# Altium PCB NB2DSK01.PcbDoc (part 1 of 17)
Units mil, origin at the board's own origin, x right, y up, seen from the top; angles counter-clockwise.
Board outline 11815 x 6500.03 mil, 8 copper layers (Top Layer, MidLayer1, MidLayer2, GND, PWR, MidLayer3, MidLayer4, Bottom Layer), stack 74.62 mil thick; 798 components, 1002 nets, 3927 pads, 3182 vias.
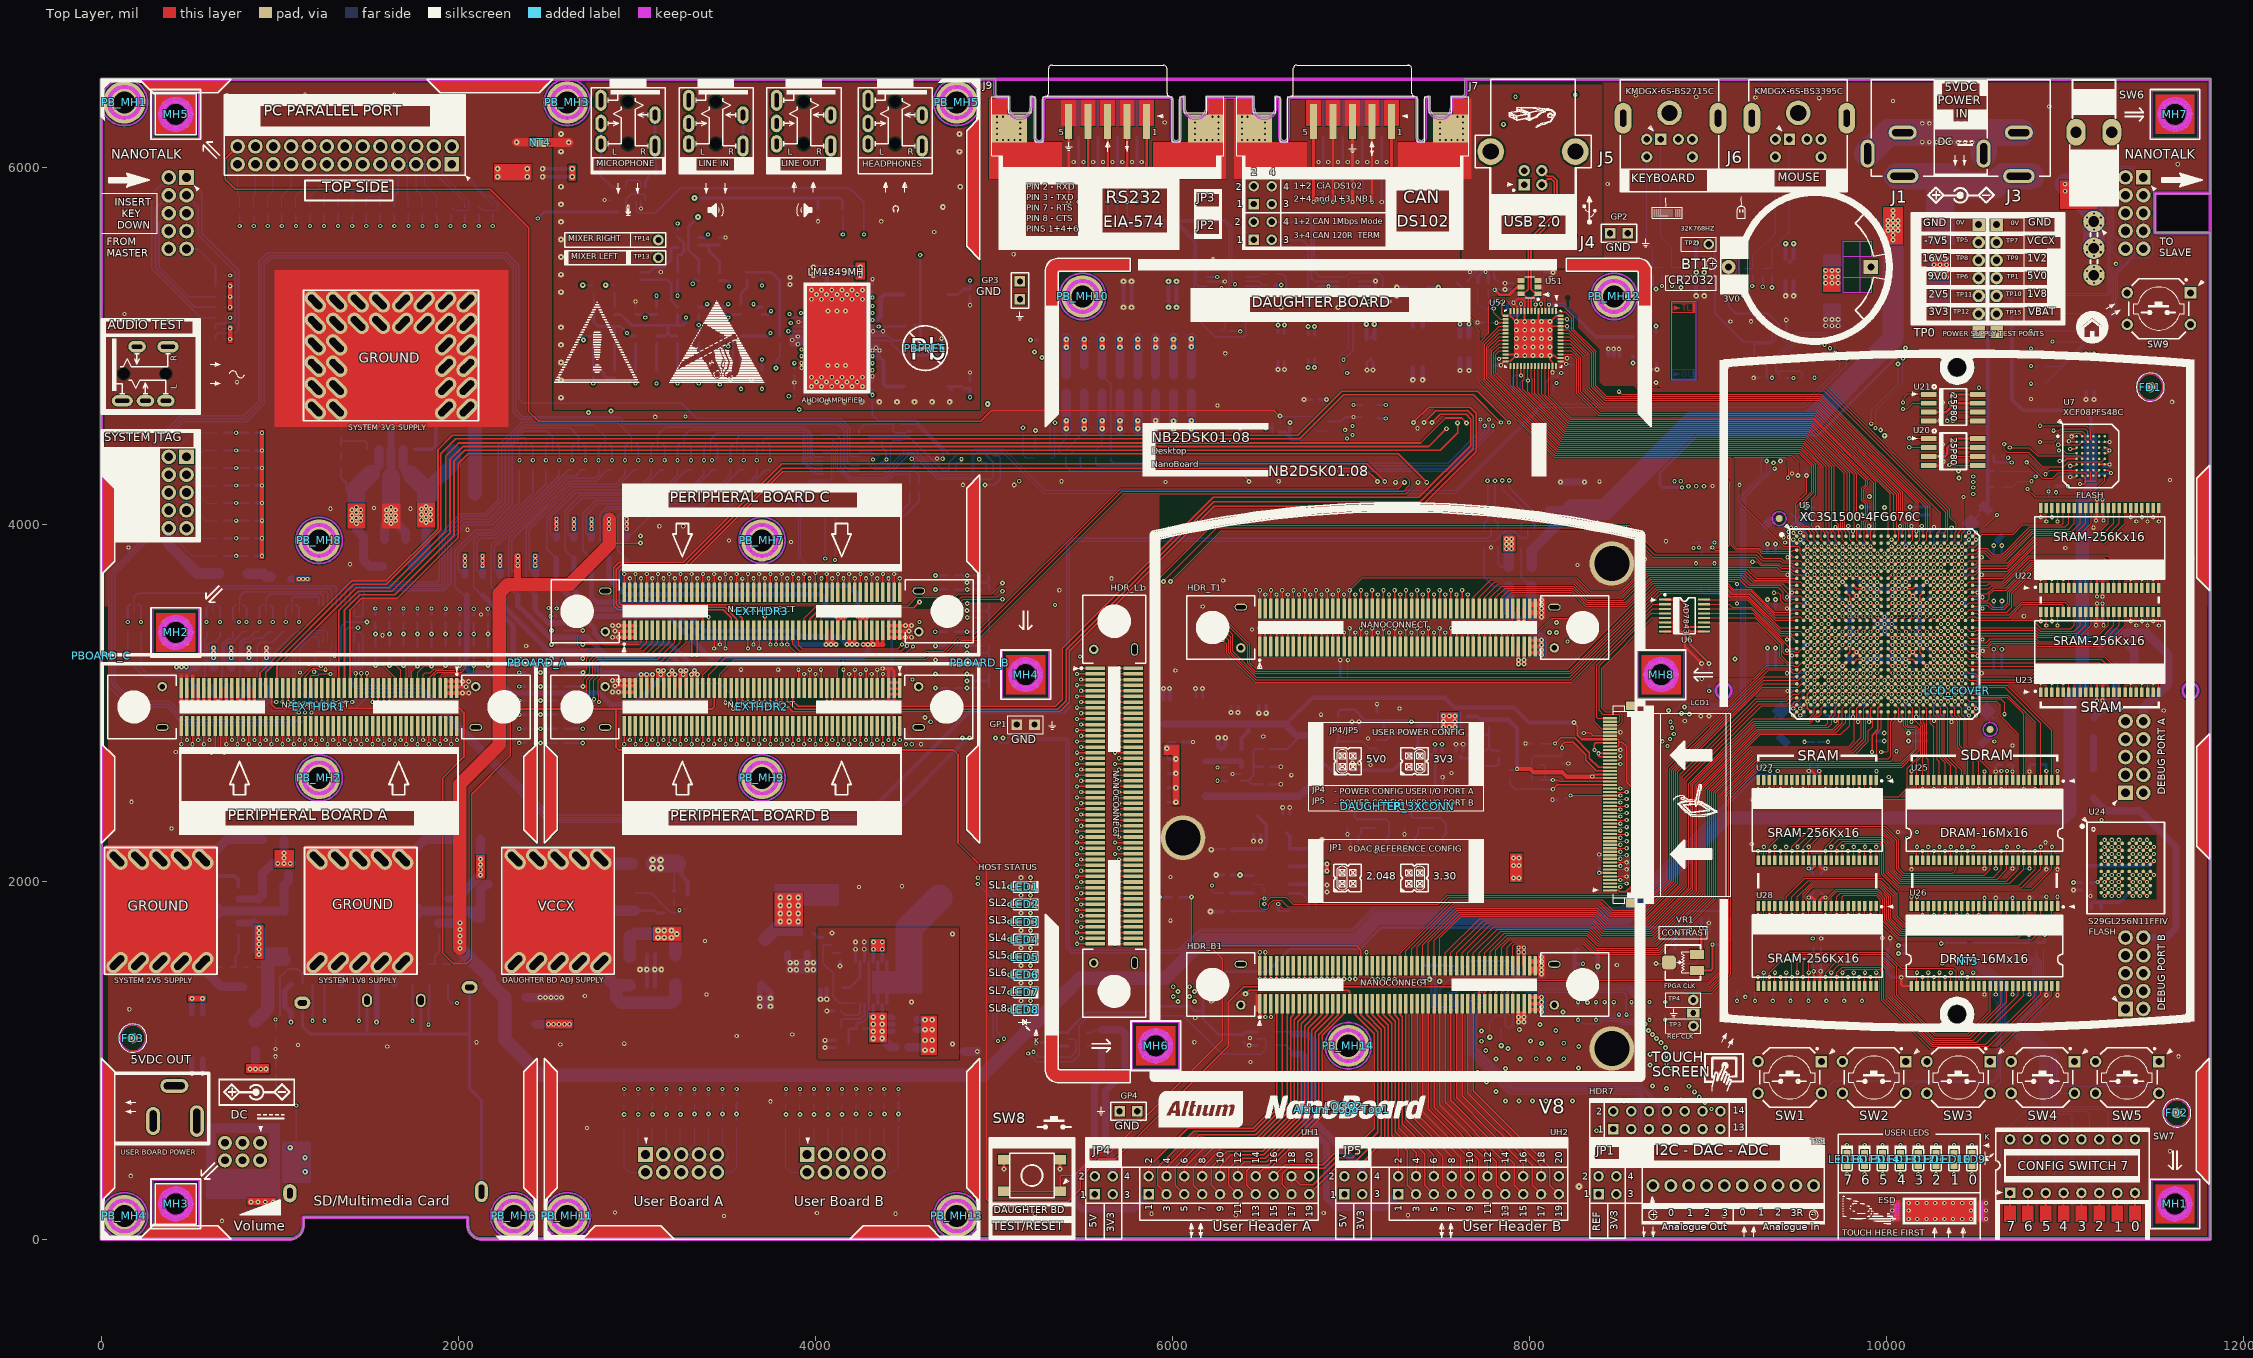
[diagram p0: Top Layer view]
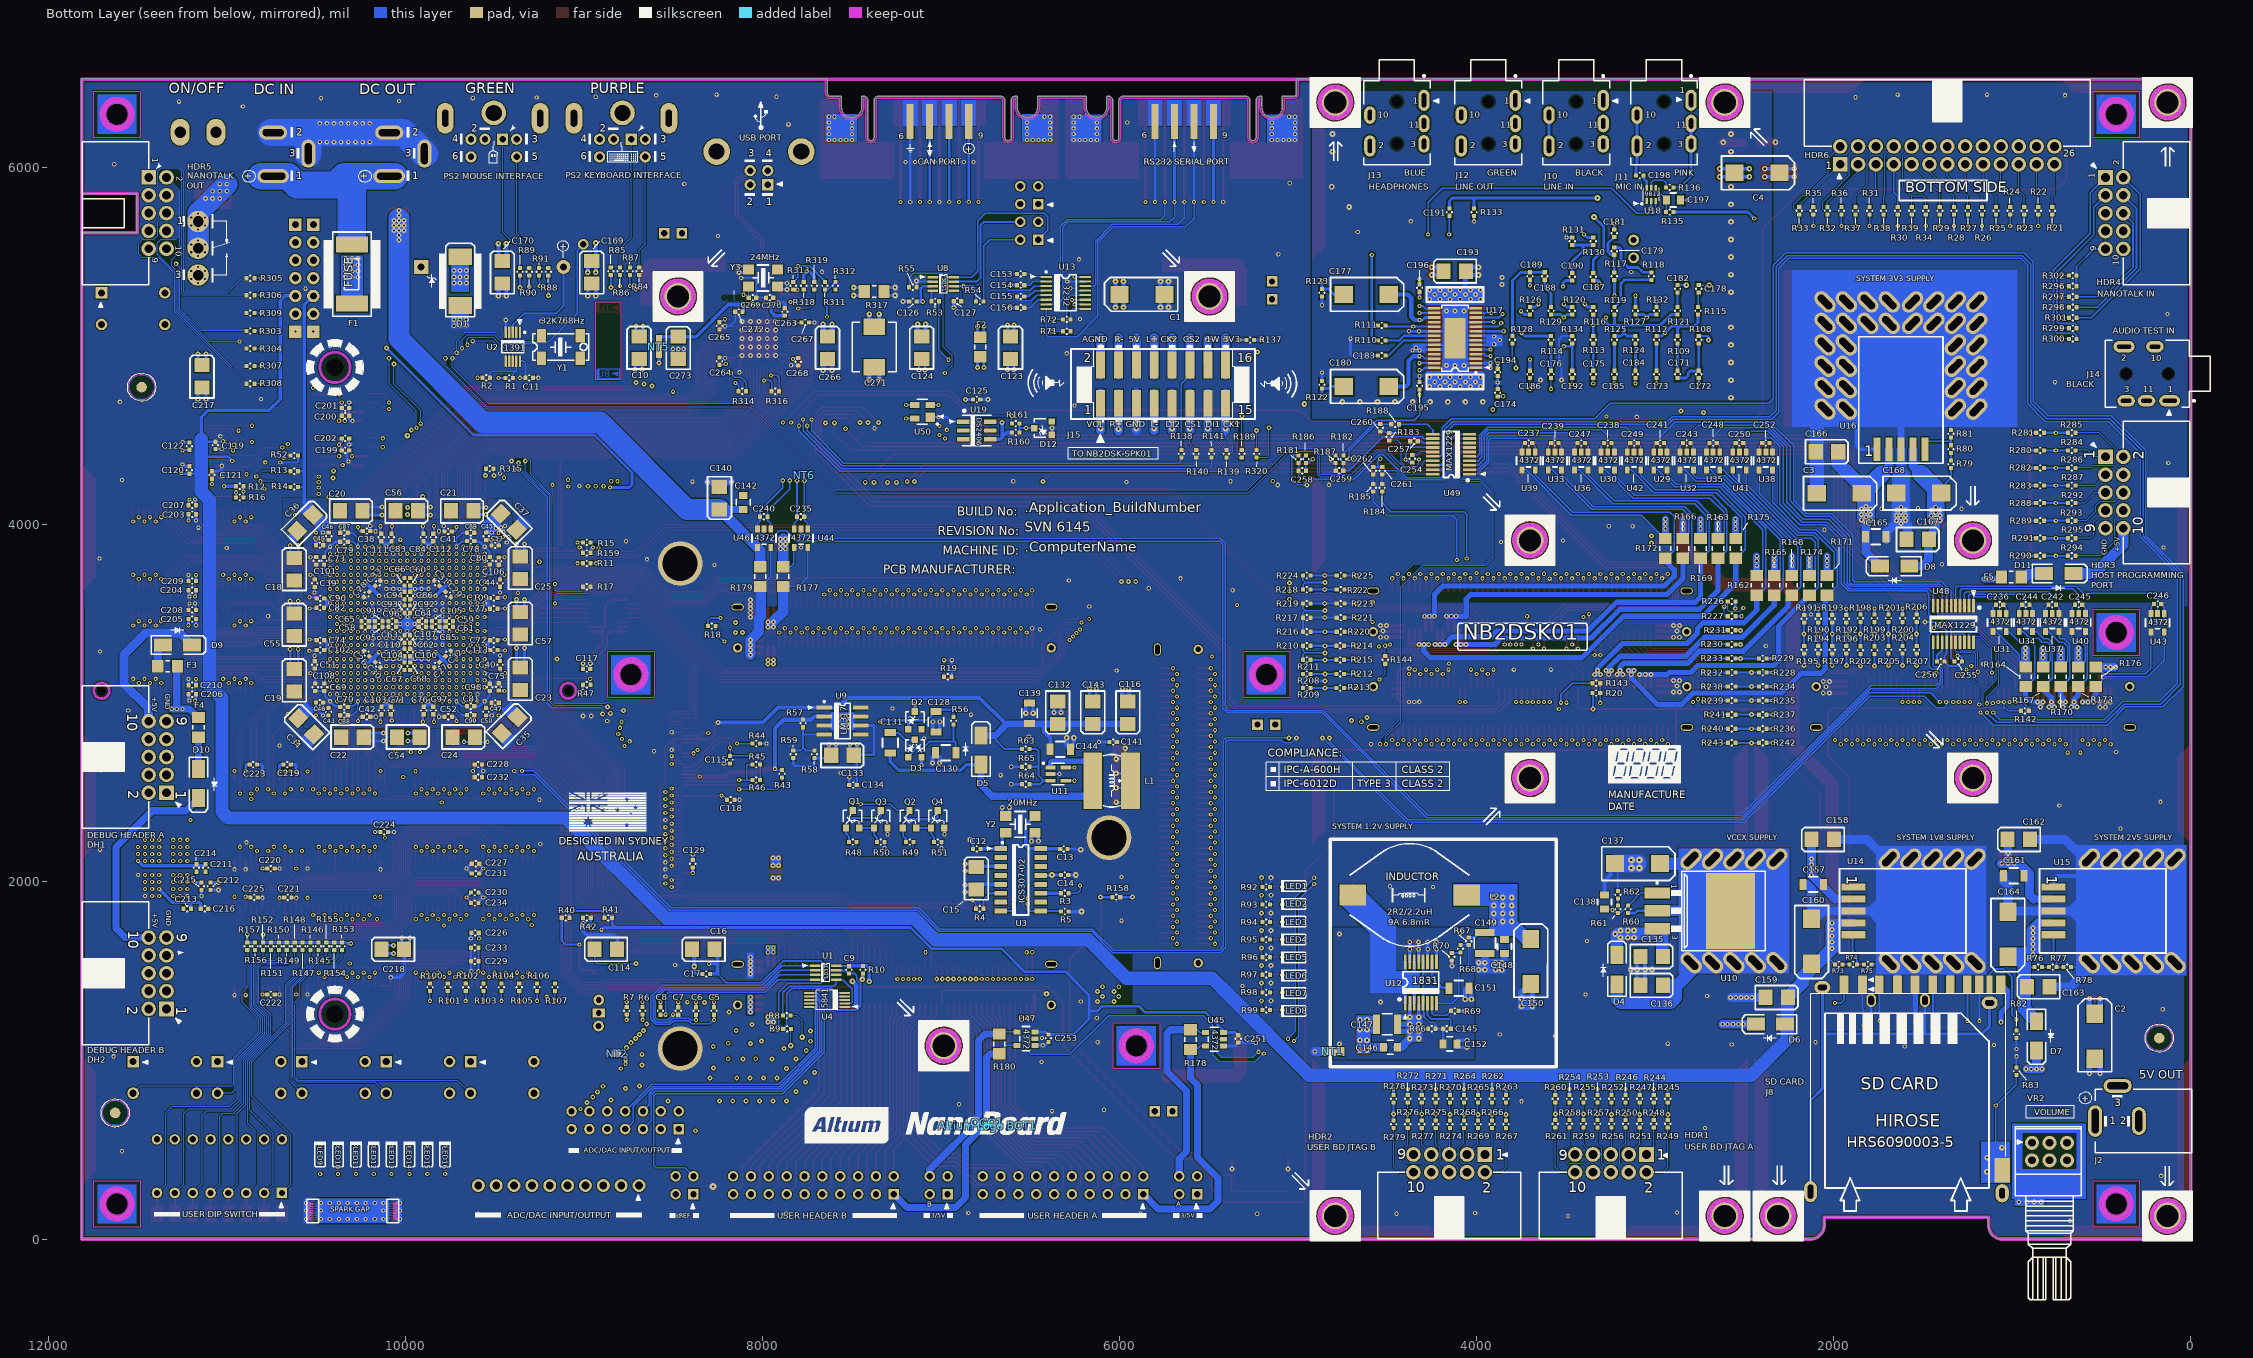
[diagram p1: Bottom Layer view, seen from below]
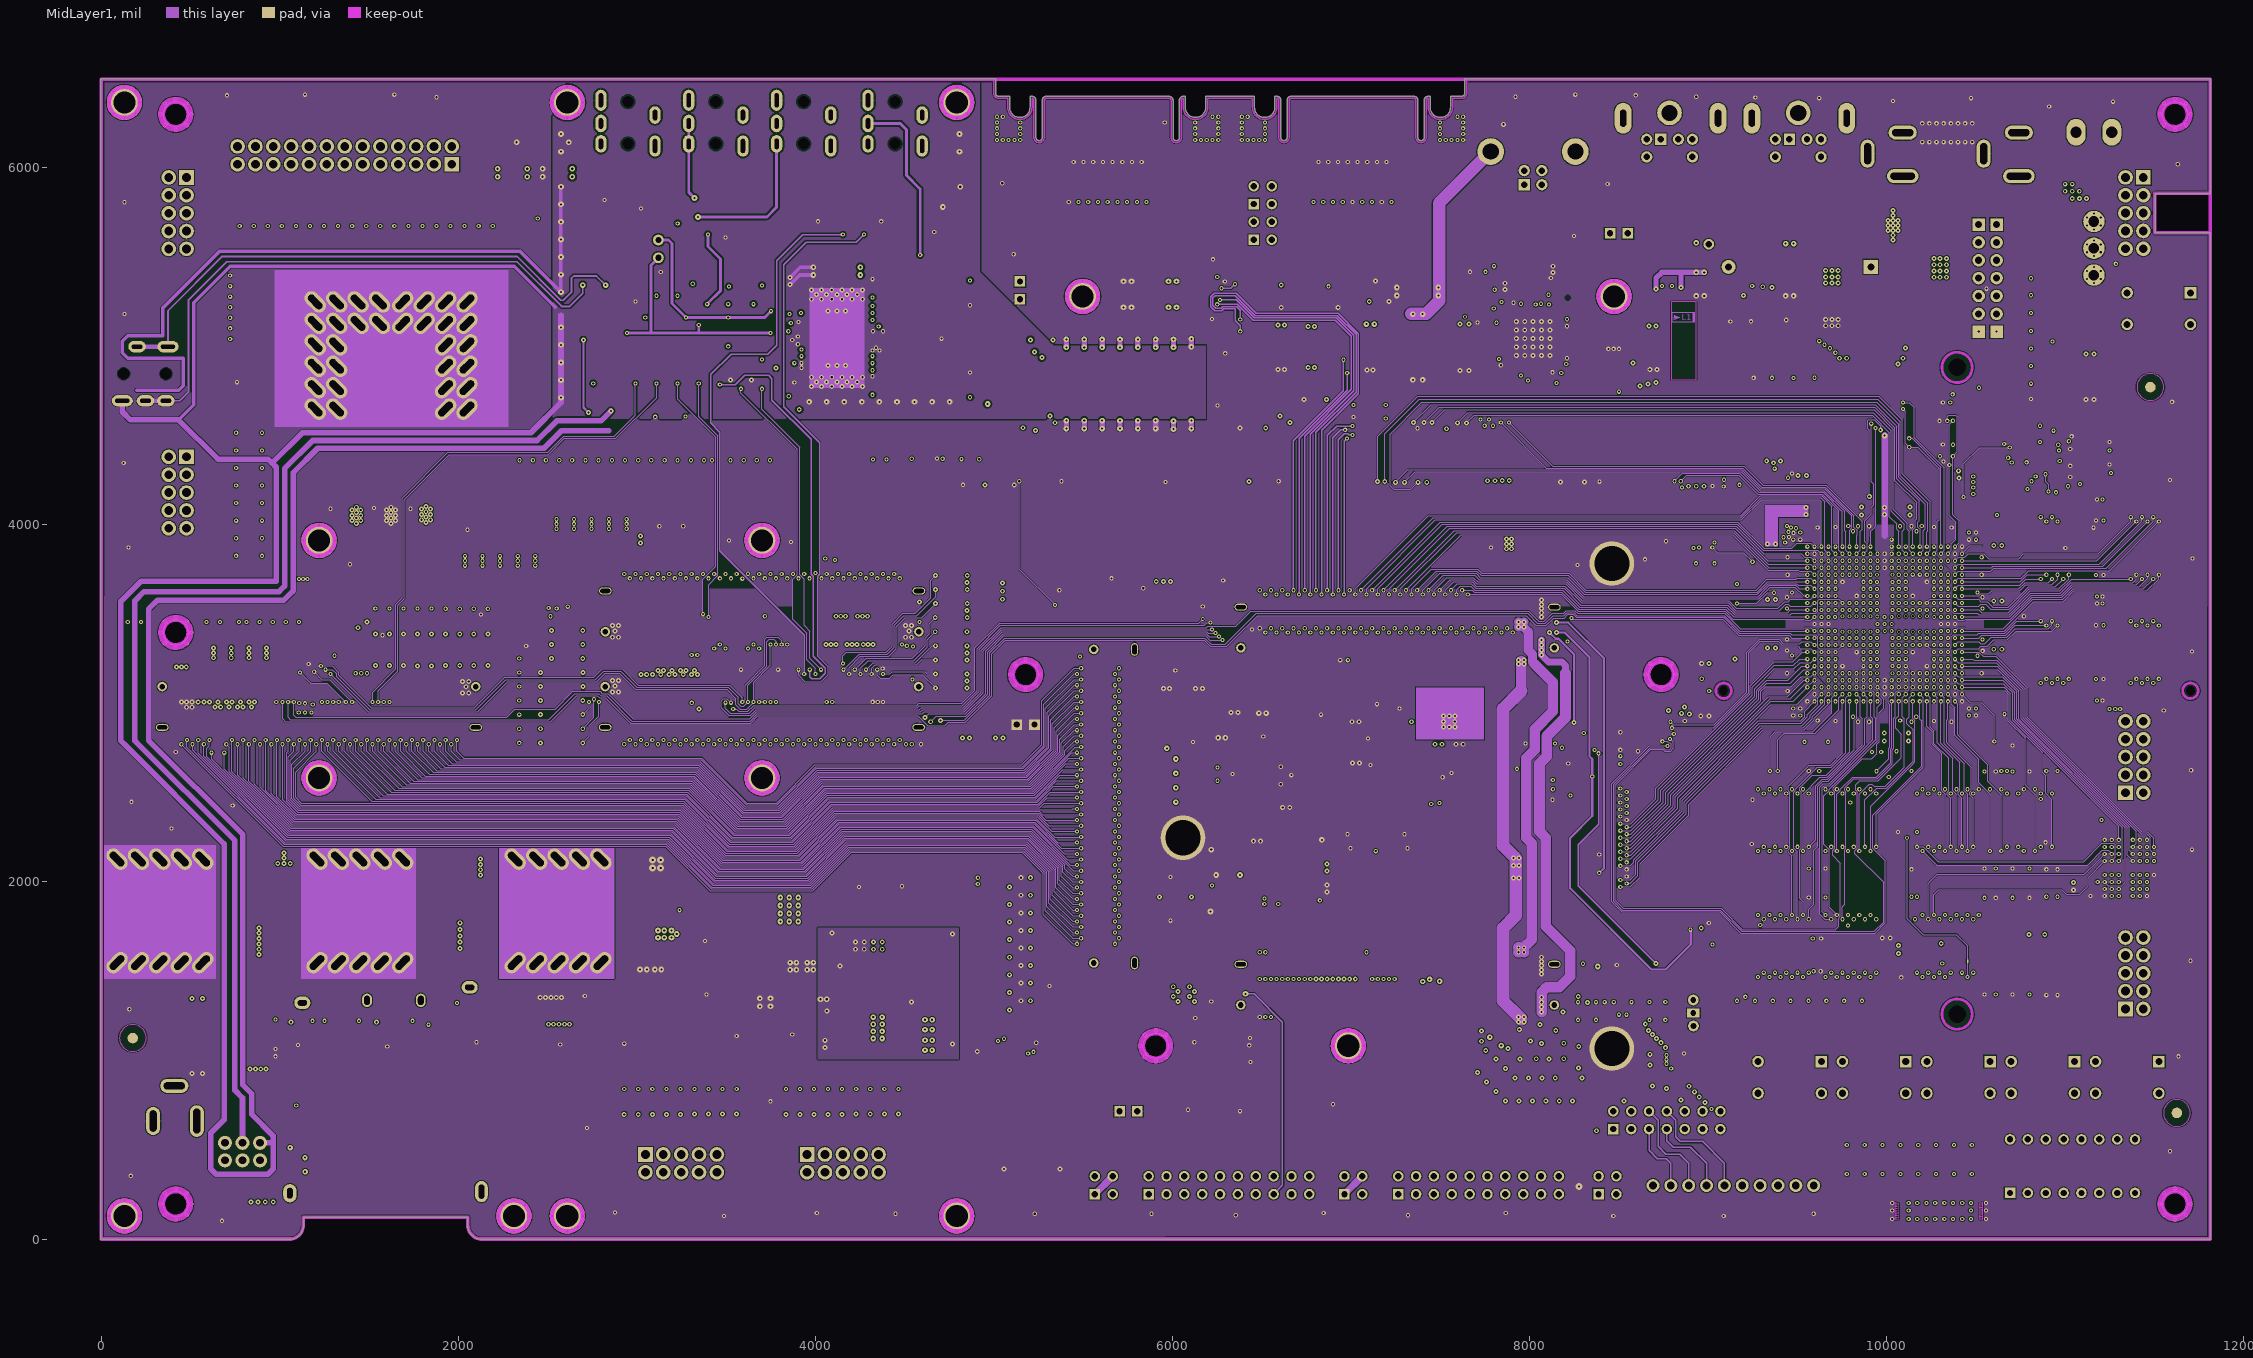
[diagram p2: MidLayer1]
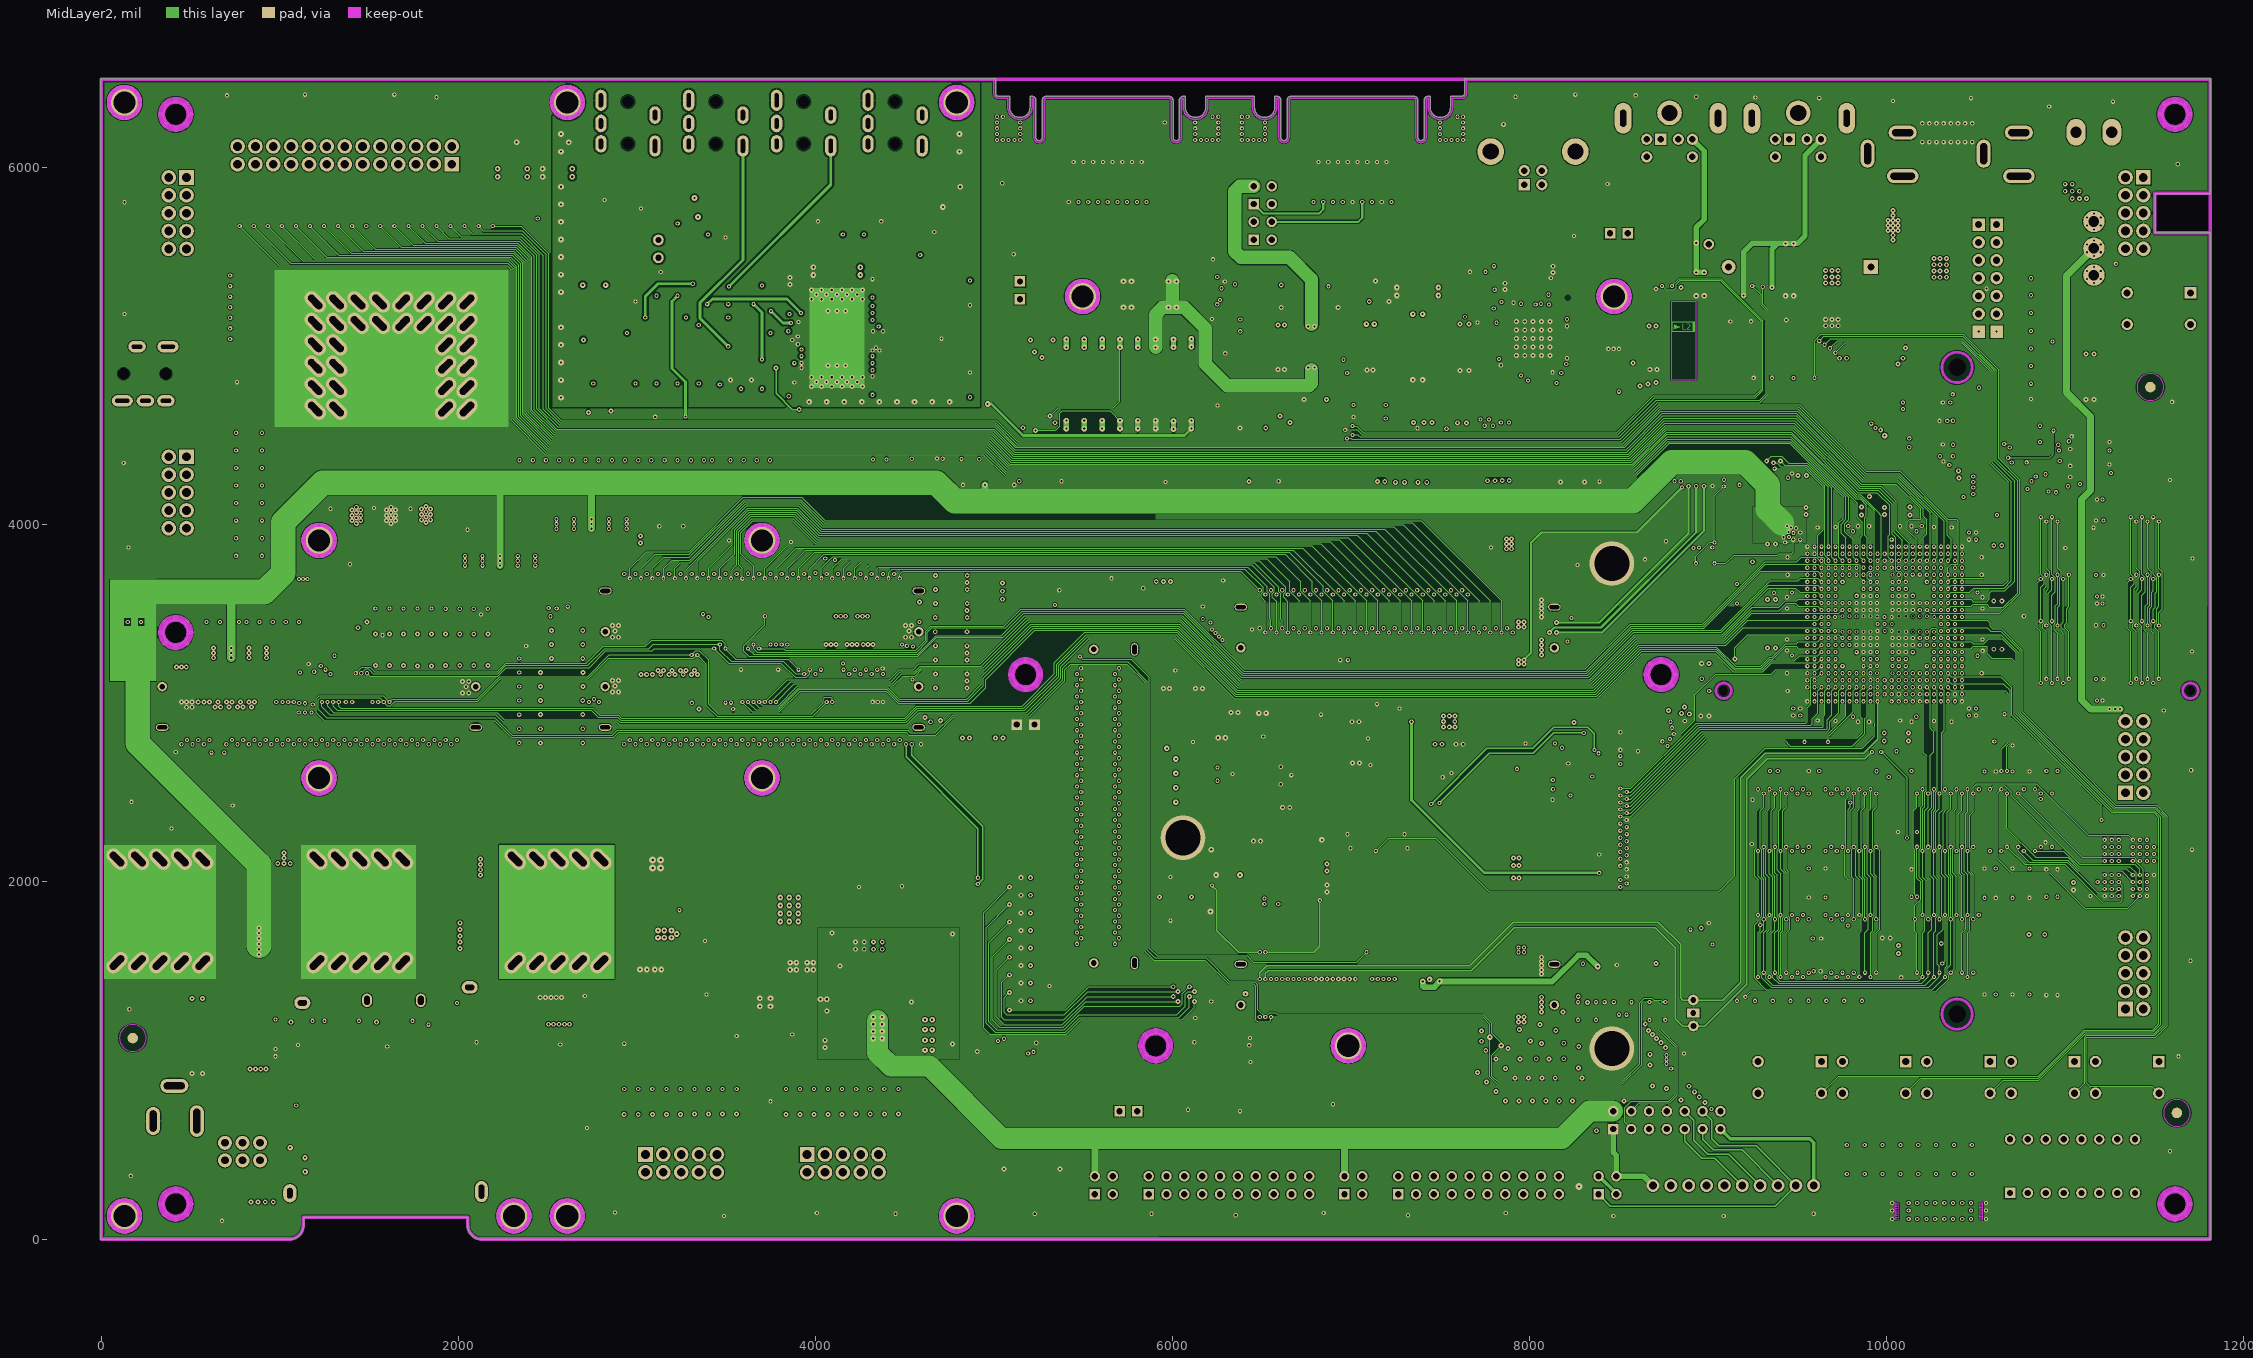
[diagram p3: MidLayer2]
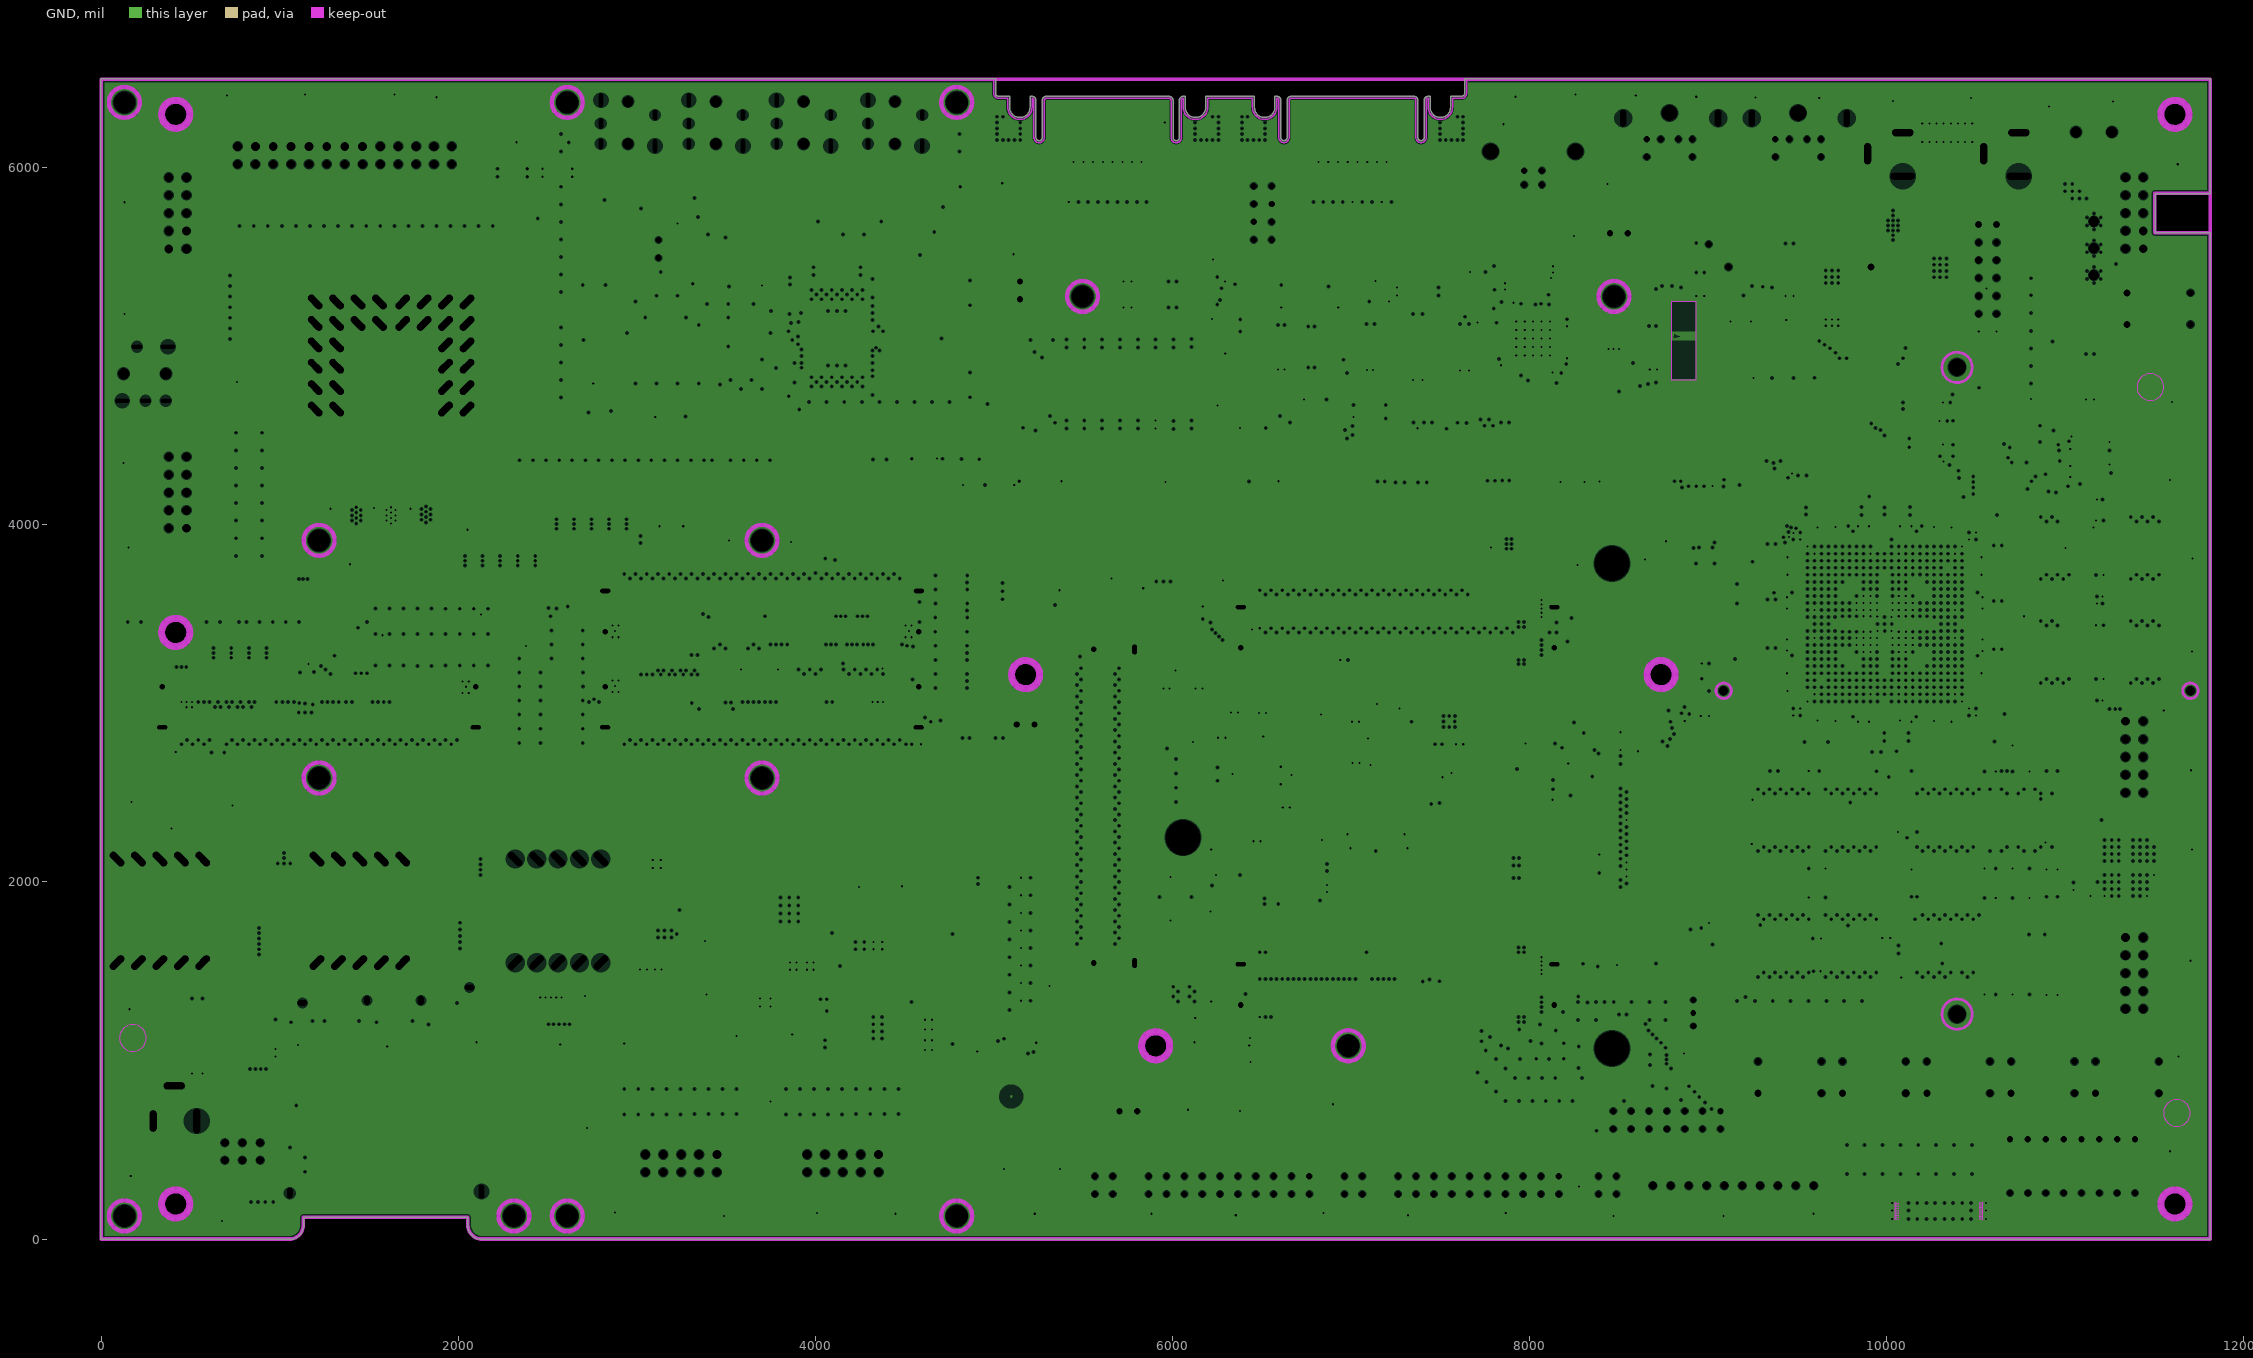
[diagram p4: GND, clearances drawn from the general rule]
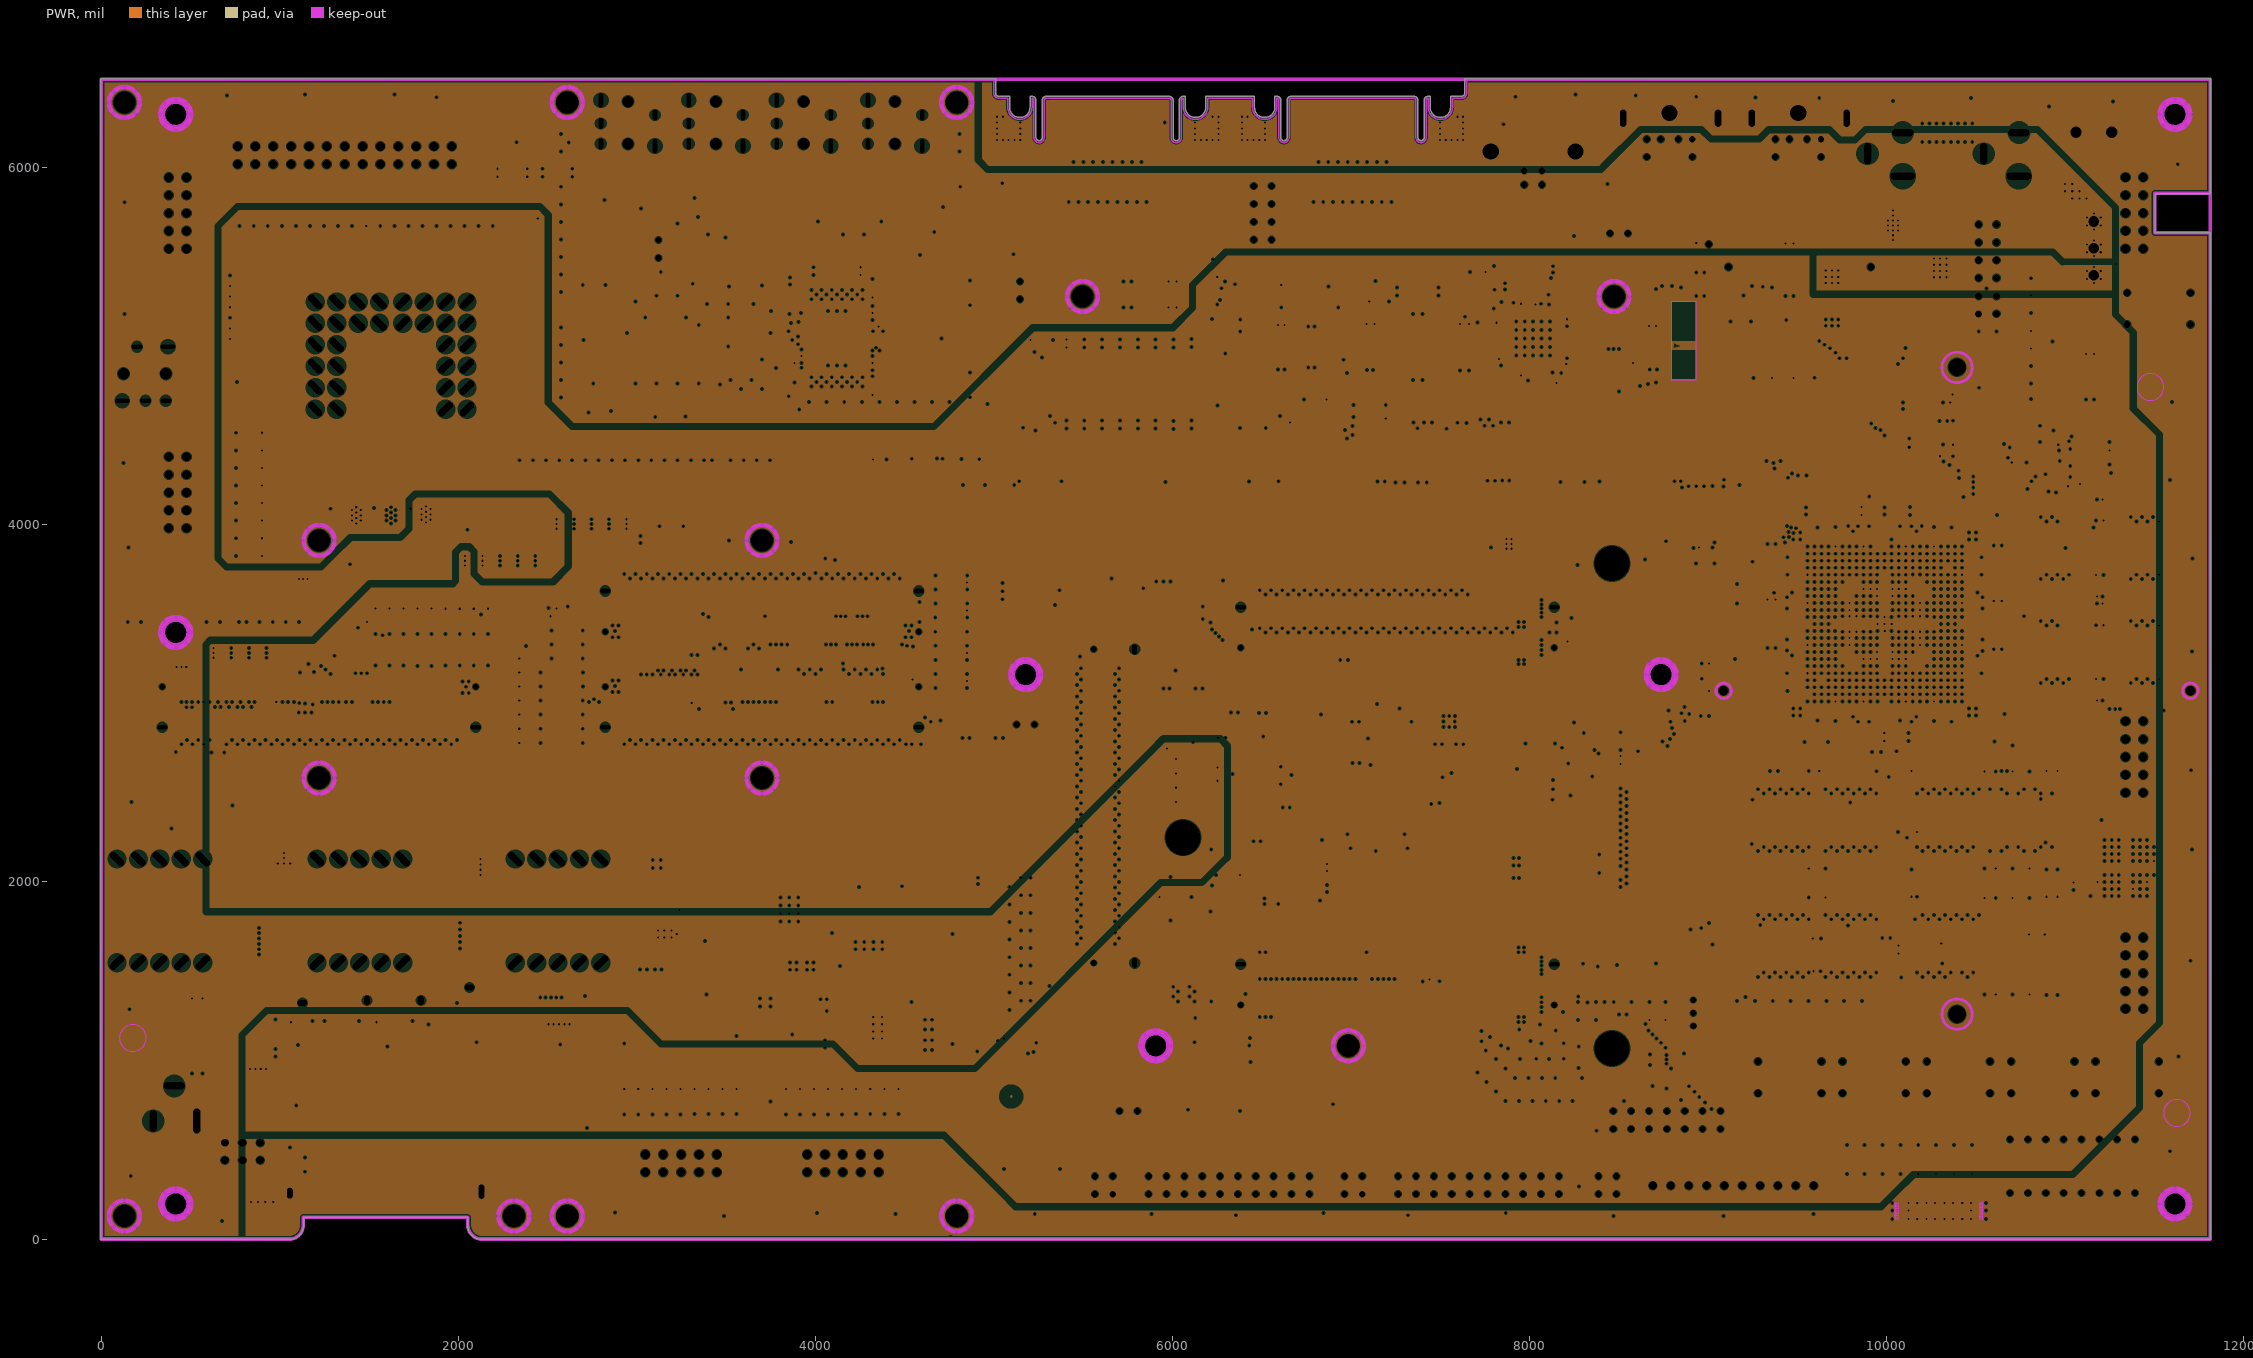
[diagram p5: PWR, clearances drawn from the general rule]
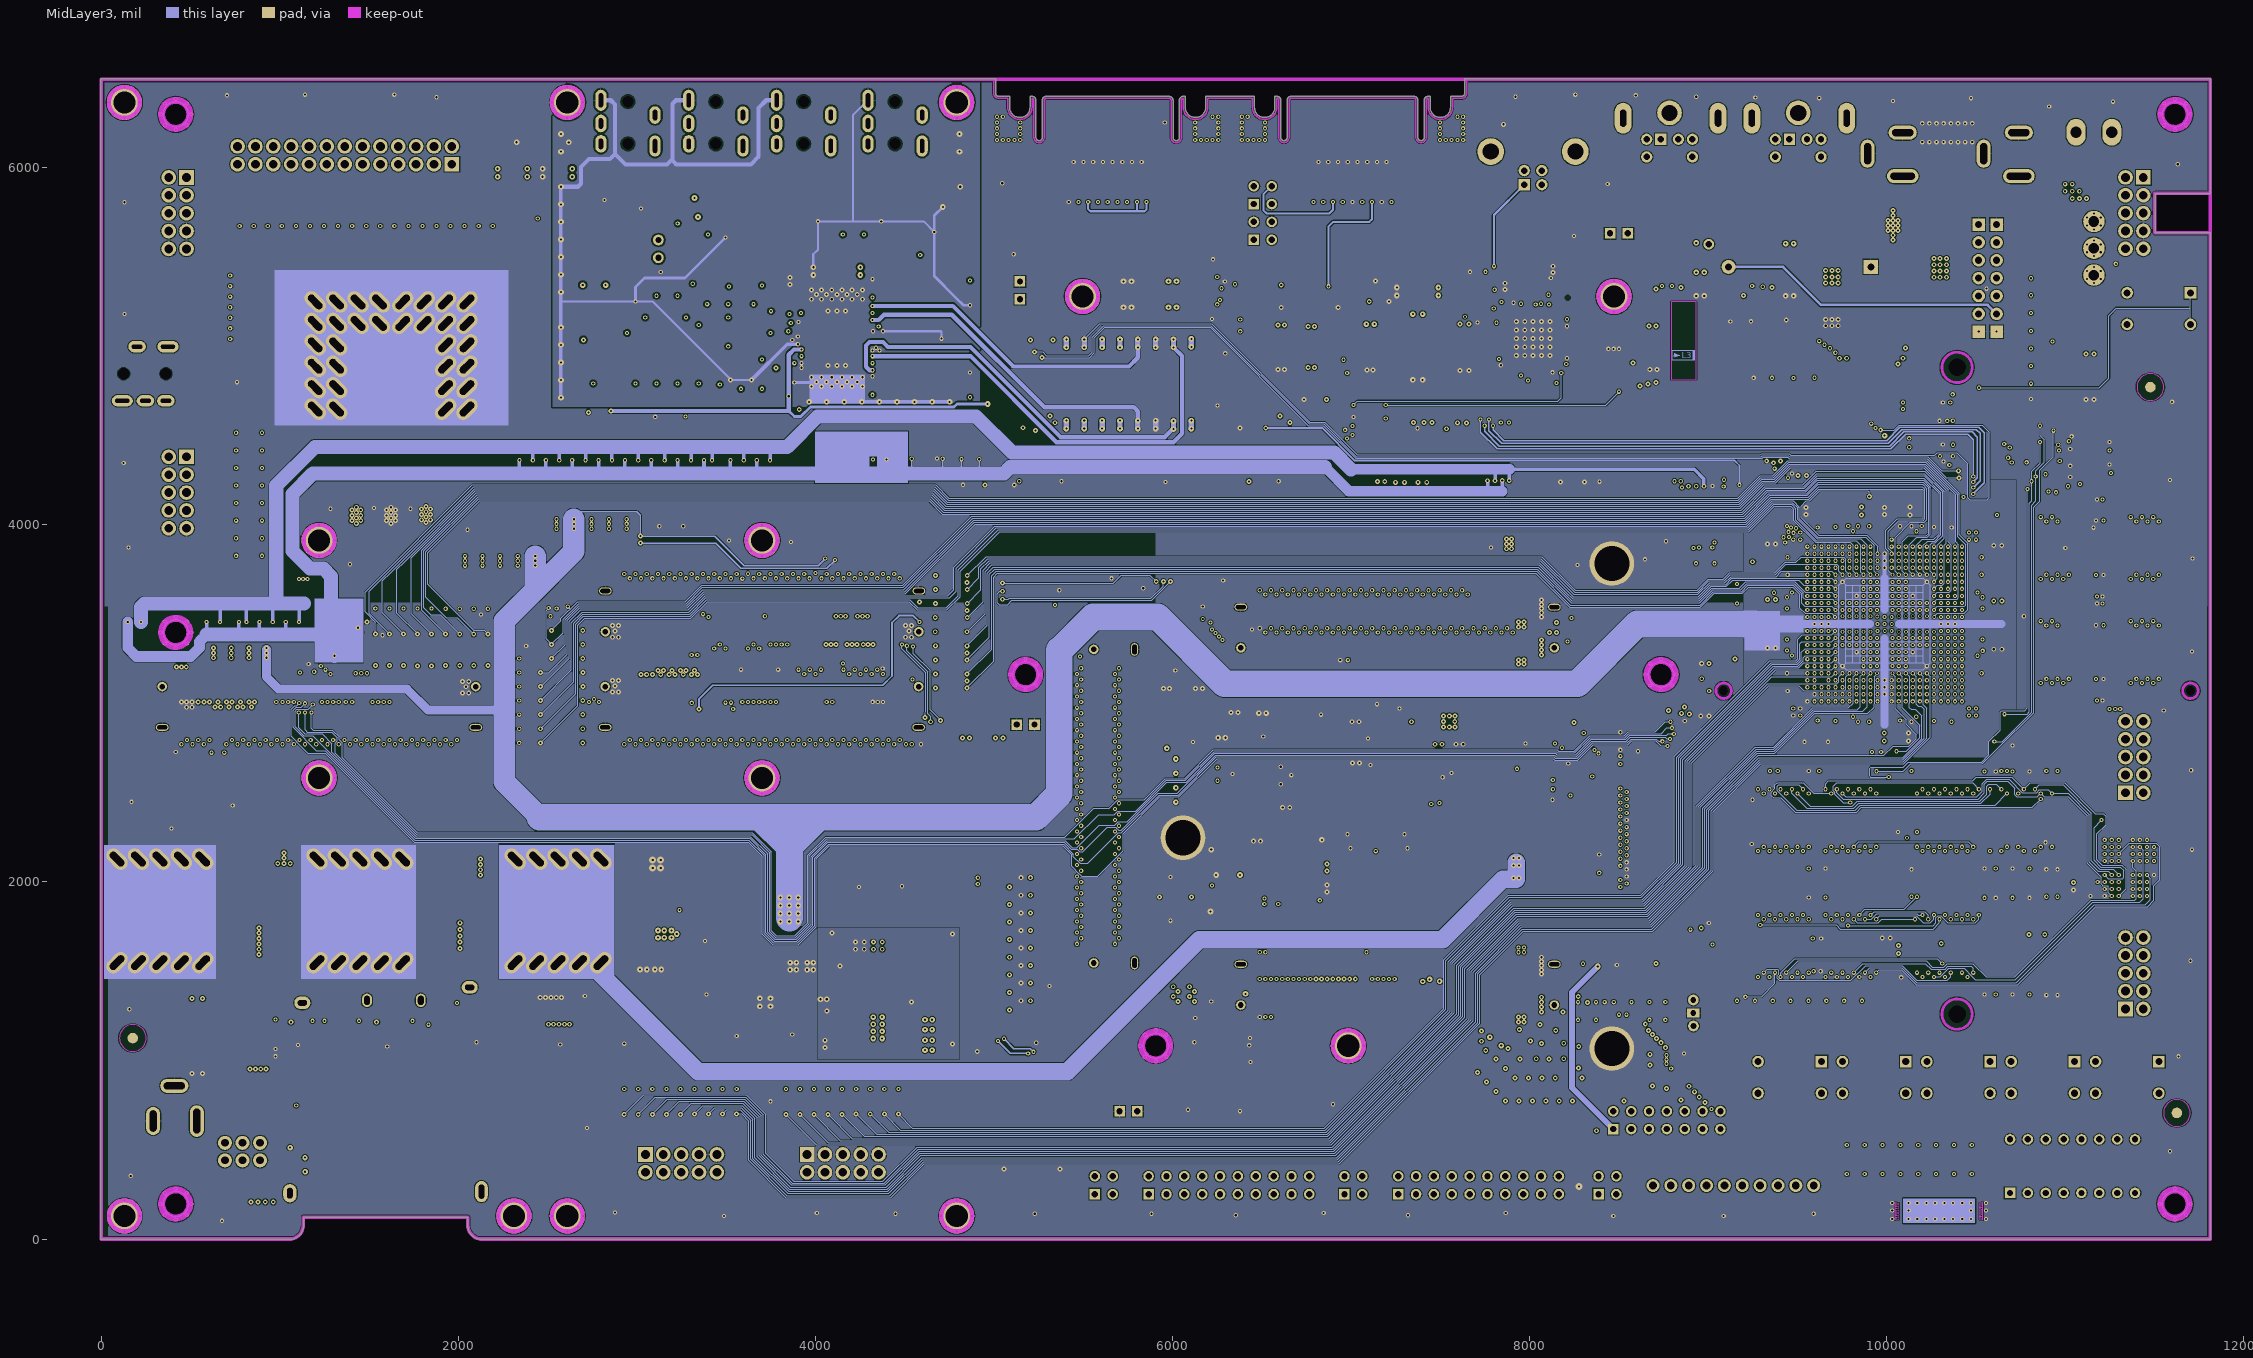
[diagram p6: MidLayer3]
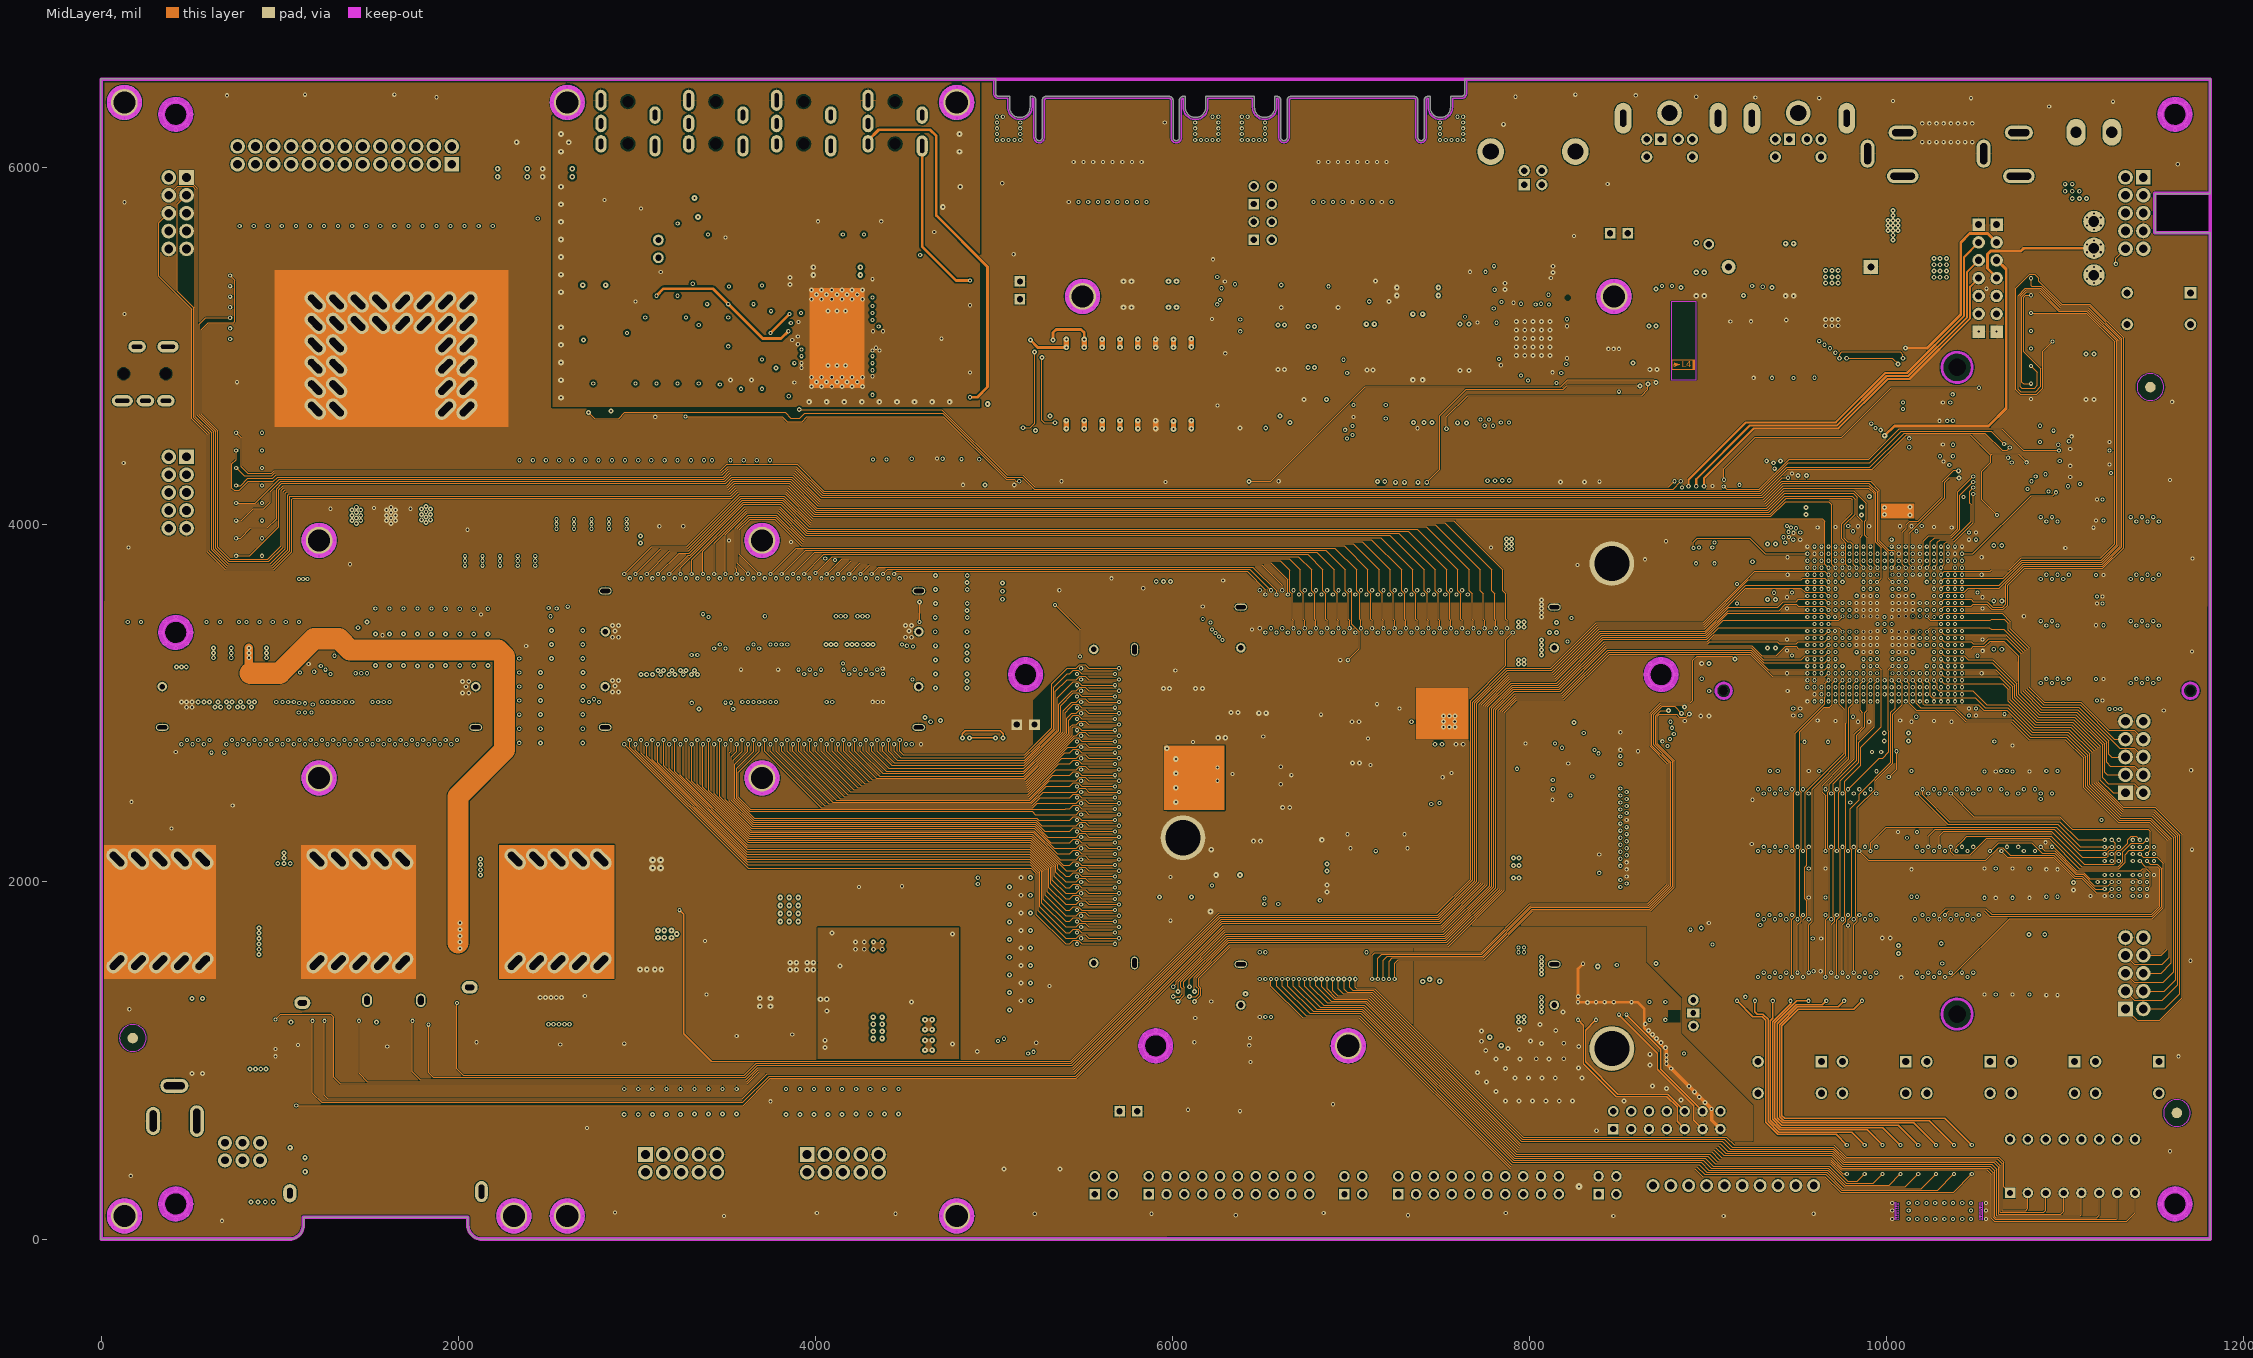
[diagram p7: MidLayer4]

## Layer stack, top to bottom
Top Layer: signal copper 1.4
Dielectric: core 9.0551, FR-4, Dk 4.8
MidLayer1: signal copper 1.4
Dielectric: prepreg 9.0551, FR-4, Dk 4.8
MidLayer2: signal copper 1.4
Dielectric: core 9.0551, FR-4, Dk 4.8
GND: plane copper 1.4173, net GND
Dielectric: prepreg 9.0551, FR-4, Dk 4.8
PWR: plane copper 1.4173, net (Multiple Nets)
Dielectric: core 9.0551, FR-4, Dk 4.8
MidLayer3: signal copper 1.4
Dielectric: prepreg 9.0551, FR-4, Dk 4.8
MidLayer4: signal copper 1.4
Dielectric: core 9.0551, FR-4, Dk 4.8
Bottom Layer: signal copper 1.4

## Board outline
0,-1.98 1053.39,-1.98 ccw(c1053.39,78.74) 1134.12,78.74 1134.12,121.47 2051.7,121.47 2051.7,78.74 ccw(c2132.42,78.74) 2132.42,-1.98 11811.02,-1.98 ccw(c11811.02,0) 11813.01,0 11813.01,5634.92 ccw(c11811.02,5634.92) 11811.02,5636.91 11503.18,5636.91 11503.18,5854.43 11811.02,5854.43 ccw(c11811.02,5856.42) 11813.01,5856.42 11813.01,6495.91 ccw(c11811.03,6496.06) 11813.01,6496.06 ccw(c11811.03,6496.06) 11811.03,6498.05 7637.8,6498.05 ccw(c7637.8,6496.06) 7635.82,6496.06 7635.82,6417.32 cw(c7618.11,6417.32) 7618.11,6399.62 7558.86,6399.62 ccw(c7558.86,6397.64) 7556.89,6397.42 7556.89,6338.58 cw(c7499.82,6338.58) 7442.75,6338.58 7442.75,6397.64 ccw(c7440.76,6397.64) 7440.76,6399.62 7431.12,6399.62 ccw(c7431.12,6377.95) 7409.45,6377.95 7409.45,6169.29 cw(c7391.75,6169.29) 7374.05,6169.29 7374.05,6377.95 ccw(c7352.38,6377.95) 7352.38,6399.62 6663.4,6399.62 ccw(c6663.4,6377.95) 6641.73,6377.95 6641.73,6169.29 cw(c6624.03,6169.29) 6606.33,6169.29 6606.33,6377.95 ccw(c6584.66,6377.95) 6584.66,6399.62 6575.02,6399.62 ccw(c6575.02,6397.64) 6573.03,6397.64 6573.03,6338.58 cw(c6515.96,6338.58) 6458.89,6338.58 6458.89,6397.64 ccw(c6456.91,6397.64) 6456.91,6399.62 6187.66,6399.62 ccw(c6187.66,6397.64) 6185.68,6397.64 6185.68,6338.58 cw(c6128.61,6338.58) 6071.53,6338.58 6071.53,6397.64 ccw(c6069.55,6397.64) 6069.55,6399.62 6059.91,6399.62 ccw(c6059.91,6377.95) 6038.24,6377.95 6038.24,6169.29 cw(c6020.54,6169.29) 6002.83,6169.29 6002.83,6377.95 ccw(c5981.16,6377.95) 5981.16,6399.62 5292.19,6399.62 ccw(c5292.19,6377.95) 5270.52,6377.95 5270.52,6169.29 cw(c5252.82,6169.29) 5235.12,6169.29 5235.12,6377.95 ccw(c5213.45,6377.95) 5213.45,6399.62 5203.8,6399.62 ccw(c5203.8,6397.64) 5201.82,6397.64 5201.82,6338.58 cw(c5144.75,6338.58) 5087.68,6338.58 5087.68,6397.64 ccw(c5085.69,6397.64) 5085.69,6399.62 5026.43,6399.62 cw(c5026.43,6417.32) 5008.73,6417.32 5008.73,6496.06 ccw(c5006.74,6496.06) 5006.74,6498.05 0,6498.05 ccw(c0,6496.06) -1.98,6496.06 -1.98,0 ccw(c0,0)

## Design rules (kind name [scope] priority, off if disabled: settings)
Clearance [InNamedPolygon('MidLayer3-AGND')] p1: gap=10
Clearance "Pad Via different nets" [IsPad vs IsVia] p2: gap=4.5
Clearance Clearance_Poly_USB [InNamedPolygon('USB-ML1-GND') Or InNamedPolygon('USB-TL-GND') Or InNamedPolygon('USB-TL-SHIELD')] p3: gap=10
Clearance Clearance_Poly_Tight [InNamedPolygon('FPGAPWR-BL-1V2') Or InNamedPolygon('FPGAPWR-BL-3V3') Or InNamedPolygon('FPGAPWR-BL-2V5A') Or InNamedPolygon('FPGAPWR-BL-2V5B') Or InNamedPolygon('FPGAPWR-BL-2V5C') Or InNamedPolygon('FPGAPWR-BL-2V5D') Or InNamedPolygon('FPGAPWR-ML1-1V2') Or InNamedPolygon('FPGAPWR-BL-2V5E') Or InNamedPolygon('FPGAPWR-BL-3V3' )] p4: gap=5
Clearance Clearance_Poly_AUGND [InPolygon And InNet(AUGND)] p5: gap=10
Clearance Clearance_PowerPolygon [InPolygon And InNetClass(PWRNET)] p6: gap=5
Clearance "Pad-Pad Clearance" [IsPad vs IsPad] p7: gap=5
Clearance "General Clearance" [All] p8: gap=5
ComponentClearance ComponentClearance_RES2RES [HasFootprint('RESC2012') vs HasFootprint('RESC2012')] p1: gap=-3.94 collisioncheckmode=3 verticalgap=10 showdistances=FALSE
ComponentClearance ComponentClearance_HDR2HDR [HasFootprint('HDR2X2') vs HasFootprint('HDR2X2')] p2: gap=-7.87 collisioncheckmode=3 verticalgap=10 showdistances=FALSE
ComponentClearance ComponentClearance_LED2LED [HasFootprint('LED2013') vs HasFootprint('LED2013')] p3: gap=-7.87 collisioncheckmode=3 verticalgap=10 showdistances=FALSE
ComponentClearance ComponentClearance_Bottom [OnBottom And (Not InComponentClass(Templates)) vs OnBottom And (Not InComponentClass(Templates))] p4: gap=3.94 collisioncheckmode=3 verticalgap=10 showdistances=FALSE
ComponentClearance ComponentClearance_Top [OnTop And (Not InComponentClass(Templates)) vs OnTop And (Not InComponentClass(Templates))] p5: gap=3.94 collisioncheckmode=3 verticalgap=10 showdistances=FALSE
DiffPairsRouting DiffPair_DiffPairsRouting [All] p1: maxlimit=12.6 minlimit=11.02 mostfreqgap=7.87 toplayer_prefgap=11.81 midlayer1_prefgap=11.81 midlayer2_prefgap=11.81 midlayer3_prefgap=11.81 midlayer4_prefgap=11.81 bottomlayer_prefgap=11.81 maxuncoupledlength=500
DiffPairsRouting PairRoute [All] p2: maxlimit=5.91 minlimit=5 mostfreqgap=5 maxuncoupledlength=393.7
FanoutControl Fanout_BGA [All] p1: bgadir=Out bgaviamode=Centered fanoutstyle=BGA fanoutdirection=OutOnly viagrid=1 // Fanout_BGA (Default Rule)
HoleSize [IsPad And (holesize <> 0)] p1: absolutevalues=TRUE maxlimit=204.72 minlimit=11.81 maxpercent=80.000 minpercent=20.000
MatchedLengths DiffPair_MatchedLengths [(IsDifferentialPair And (Name = 'USB_DP'))] p1: tolerance=393.7 checknetsindiffpair=TRUE checkdiffpairvsdiffpair=TRUE checkothers=TRUE
MatchedLengths DiffPair_MatchedLengths_1 [(IsDifferentialPair And (Name = 'DIFF_RX1'))] p2: tolerance=1000 checknetsindiffpair=TRUE checkdiffpairvsdiffpair=TRUE checkothers=TRUE
MinimumAnnularRing [PadIsPlated And (Name <> 'Y1_RT')] p1 off: minimumring=7.87
PlaneClearance [All] p1: clearance=5
PlaneConnect vias [IsVIA] p1: planeconnectstyle=Direct reliefexpansion=20 reliefentries=4 reliefconductorwidth=10 reliefairgap=10
PlaneConnect "PlaneConnect of large Pads" [(InComponent('DAUGHTER_3XCONN'))] p2: planeconnectstyle=Direct reliefexpansion=20 reliefentries=4 reliefconductorwidth=10 reliefairgap=10
PlaneConnect [All] p3: planeconnectstyle=Relief reliefexpansion=10 reliefentries=4 reliefconductorwidth=10 reliefairgap=5
PolygonConnect "Direct connection for large pads" [(InComponent('DAUGHTER_3XCONN'))] p1: connectstyle=Direct reliefconductorwidth=10 reliefentries=4 polygonreliefangle="90 Angle"
PolygonConnect "PolygonConnect - Heatsink" [IsVia] p2: connectstyle=Direct reliefconductorwidth=10 reliefentries=4 polygonreliefangle="90 Angle"
PolygonConnect [All] p3: connectstyle=Relief reliefconductorwidth=6 reliefentries=4 polygonreliefangle="90 Angle"
RoomDefinition U_AUTO_JTAG_UBA [InComponentClass('U_AUTO_JTAG_UBA')] p1: confinementstyle=ConfineIn formatcopy=TRUE lockcomponents=FALSE outline 3598.43,531.5 2834.65,531.5 2834.65,866.14 3598.43,866.14
RoomDefinition U_AUTO_JTAG_UBB [InComponentClass('U_AUTO_JTAG_UBB')] p2: confinementstyle=ConfineIn formatcopy=FALSE lockcomponents=FALSE outline 4562.99,531.5 3779.53,531.5 3779.53,866.14 4562.99,866.14
RoomDefinition AUTO_EXC [InComponentClass('AUTO_EXC')] p3: confinementstyle=ConfineIn formatcopy=TRUE lockcomponents=FALSE outline 2688.98,2732.28 2688.98,3456.69 2354.33,3456.69 2354.33,2732.28
RoomDefinition AUTO_EXB [InComponentClass('AUTO_EXB')] p4: confinementstyle=ConfineIn formatcopy=TRUE lockcomponents=FALSE outline 4681.1,3763.78 4681.1,3039.37 5015.75,3039.37 5015.75,3763.78
RoomDefinition AUTO_EXA [InComponentClass('AUTO_EXA')] p5: confinementstyle=ConfineIn formatcopy=TRUE lockcomponents=FALSE outline 1409.45,3220.47 2133.86,3220.47 2133.86,3555.12 1409.45,3555.12
RoutingVias [All] p1: holewidth=11.81 width=27.56 viastyle="Through Hole" minholewidth=11.81 minwidth=21.65 maxholewidth=39.37 maxwidth=78.74
ShortCircuit ShortCircuit_1 [Net = 'No Net' vs Net = 'No Net'] p1: allowed=TRUE
ShortCircuit [All] p2: allowed=FALSE
SolderMaskExpansion SolderMaskExpansion_Vias [IsVia] p1: expansion=-30
SolderMaskExpansion [All] p2: expansion=1.5
TestPointUsage [All] p1 off: valid=0 allowmultiple=FALSE
Testpoint [All] p1 off: side=15 testpointundercomponent=TRUE minsize=40 maxsize=100 preferedsize=60 minholesize=0 maxholesize=40 preferedholesize=32 testpointgrid=1 style=1023 order=0-112345678
Width DiffPair_Width [InDifferentialPair('USB_DP')] p1: maxlimit=12.6 minlimit=11.02 preferedwidth=11.81
Width Width_DiffPair [InNetClass('DiffPairs')] p2: maxlimit=7.09 minlimit=7.09 preferedwidth=7.09
Width [All] p3: maxlimit=157.48 minlimit=5 preferedwidth=10 toplayer_maxwidth=157.48 midlayer1_maxwidth=157.48 midlayer2_maxwidth=157.48 midlayer3_maxwidth=157.48 midlayer4_maxwidth=157.48 bottomlayer_maxwidth=157.48 minimp=50.000000 maximp=50.000000 favimp=50.000000
12 further rules are at their usual default settings.

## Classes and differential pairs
net class SPK: SPK.SPK_L+ SPK.SPK_L- SPK.SPK_R+ SPK.SPK_R- SPK.VOL
net class EXTCTRL: EXTCTRL#.1WIRE EXTCTRL.CS1_N EXTCTRL.CS2_N EXTCTRL.DIN1 EXTCTRL.DIN2 EXTCTRL.SCK1 EXTCTRL.SCK2
net class EXTCTRL#: EXTCTRL#.1WIRE EXTCTRL#.CS1_N EXTCTRL#.CS2_N EXTCTRL#.DIN1 EXTCTRL#.DIN2 EXTCTRL#.SCK1 EXTCTRL#.SCK2
net class AUDIO: AUDIO.AMP_L AUDIO.AMP_R AUDIO.HP_L AUDIO.HP_R AUDIO.HP_SENSE AUDIO.LIN_L AUDIO.LIN_R AUDIO.LOUT_L AUDIO.LOUT_R AUDIO.MIC "AUDIO.PARASITE PWR"
component class SPK: J15
component class NB2_EXTEND: R137 R138 R139 R140 R141 R189 R320
component class MICAMP: C197 C198 R135 R136 U18
component class CON_AUDIO: J10 J11 J12 J13 J14
component class AMP_LM4849: C174 C177 C180 C183 C187 C190 C193 C194 C195 C196 R110 R111 R116 R120 R122 R123 R127 R130 R131 R132 U17
component class USB_TXRX: C263 C264 C265 C266 C267 C268 C269 C270 C271 C272 C273 NT5 R311 R312 R313 R314 R315 R316 R317 R318 R319 U50 U51 U52 Y3
net class TFT_SPI: TFT_SPI.BUSY TFT_SPI.CLK TFT_SPI.CS_N TFT_SPI.DIN TFT_SPI.DOUT
component class U_NB2_DBCON: FP1 HDR_B1 HDR_L1 HDR_T1 R18 R19 R20
net class TFT#.CL[3..1]: TFT#.CL1 TFT#.CL2 TFT#.CL3
net class DAU_TFT.CL[3..1]: DAU_TFT.CL1 DAU_TFT.CL2 DAU_TFT.CL3
net class PDA: PDA.D0 PDA.D1 PDA.D2 PDA.D3 PDA.D4
net class PDA.D[4..0]: PDA.D0 PDA.D1 PDA.D2 PDA.D3 PDA.D4
net class SW[4..0]: SW0 SW1 SW2 SW3 SW4 SW5 SW6
component class CON_UBB: HDR2
component class CON_UBA: HDR1
component class CURR: C235 C236 C237 C238 C239 C240 C241 C242 C243 C244 C245 C246 C247 C248 C249 C250 C251 C252 C253 C254 C255 C256 C257 C258 C259 C260 C261 C262 NT6 R162 R163 R164 R165 R166 R167 R168 R169 R170 R171 R172 R173 R174 R175 R176 R177 R178 R179 R180 R181 R182 R183 R184 R185 R186 R187 R188 U29 U30 U31 U32 U33 U34 U35 U36 U37 U38 U39 U40 U41 U42 U43 U44 U45 U46 U47 U48 U49
component class FPGA_1: NT3 R17 TP3 TP4 U5
channel class JTAG_ALTIUM_AUTO: "JTAG CONFIG1" "JTAG CONFIG2" "JTAG CONFIG3" USER_BOARD_A USER_BOARD_B
component class NANOTALK: R296 R297 R298 R299 R300 R301 R302 R303 R304 R305 R306 R307 R308 R309
net class SRAM: SRAM.A0 SRAM.A1 SRAM.A2 SRAM.A3 SRAM.A4 SRAM.A5 SRAM.A6 SRAM.A7 SRAM.A8 SRAM.A9 SRAM.A10 SRAM.A11 SRAM.A12 SRAM.A13 SRAM.A14 SRAM.A15 SRAM.A16 SRAM.A17 SRAM.A18 SRAM.D0 SRAM.D1 SRAM.D2 SRAM.D3 SRAM.D4 SRAM.D5 SRAM.D6 SRAM.D7 SRAM.D8 SRAM.D9 SRAM.D10 SRAM.D11 SRAM.D12 SRAM.D13 SRAM.D14 SRAM.D15 SRAM.D16 SRAM.D17 SRAM.D18 SRAM.D19 SRAM.D20 SRAM.D21 SRAM.D22 SRAM.D23 SRAM.D24 SRAM.D25 SRAM.D26 SRAM.D27 SRAM.D28 SRAM.D29 SRAM.D30 SRAM.D31 SRAM.NBE0 SRAM.NBE1 SRAM.NBE2 SRAM.NBE3 SRAM.NCS SRAM.NOE SRAM.NWE
net class SFLASH: SFLASH.DIN SFLASH.DOUT SFLASH.FLASH1_CS_N SFLASH.FLASH2_CS_N SFLASH.SCLK
net class MEM.BUS_D[31..0]: MEM.BUS_D0 MEM.BUS_D1 MEM.BUS_D2 MEM.BUS_D3 MEM.BUS_D4 MEM.BUS_D5 MEM.BUS_D6 MEM.BUS_D7 MEM.BUS_D8 MEM.BUS_D9 MEM.BUS_D10 MEM.BUS_D11 MEM.BUS_D12 MEM.BUS_D13 MEM.BUS_D14 MEM.BUS_D15 MEM.BUS_D16 MEM.BUS_D17 MEM.BUS_D18 MEM.BUS_D19 MEM.BUS_D20 MEM.BUS_D21 MEM.BUS_D22 MEM.BUS_D23 MEM.BUS_D24 MEM.BUS_D25 MEM.BUS_D26 MEM.BUS_D27 MEM.BUS_D28 MEM.BUS_D29 MEM.BUS_D30 MEM.BUS_D31
net class MEM.BUS_A[24..1]: MEM.BUS_A1 MEM.BUS_A2 MEM.BUS_A3 MEM.BUS_A4 MEM.BUS_A5 MEM.BUS_A6 MEM.BUS_A7 MEM.BUS_A8 MEM.BUS_A9 MEM.BUS_A10 MEM.BUS_A11 MEM.BUS_A12 MEM.BUS_A13 MEM.BUS_A14 MEM.BUS_A15 MEM.BUS_A16 MEM.BUS_A17 MEM.BUS_A18 MEM.BUS_A19 MEM.BUS_A20 MEM.BUS_A21 MEM.BUS_A22 MEM.BUS_A23 MEM.BUS_A24
net class CM_SRAM: MEM.BUS_A2 MEM.BUS_A3 MEM.BUS_A4 MEM.BUS_A5 MEM.BUS_A6 MEM.BUS_A7 MEM.BUS_A8 MEM.BUS_A9 MEM.BUS_A10 MEM.BUS_A11 MEM.BUS_A12 MEM.BUS_A13 MEM.BUS_A14 MEM.BUS_A15 MEM.BUS_A16 MEM.BUS_A17 MEM.BUS_A18 MEM.BUS_A19 MEM.BUS_A20 MEM.BUS_D0 MEM.BUS_D1 MEM.BUS_D2 MEM.BUS_D3 MEM.BUS_D4 MEM.BUS_D5 MEM.BUS_D6 MEM.BUS_D7 MEM.BUS_D8 MEM.BUS_D9 MEM.BUS_D10 MEM.BUS_D11 MEM.BUS_D12 MEM.BUS_D13 MEM.BUS_D14 MEM.BUS_D15 MEM.BUS_D16 MEM.BUS_D17 MEM.BUS_D18 MEM.BUS_D19 MEM.BUS_D20 MEM.BUS_D21 MEM.BUS_D22 MEM.BUS_D23 MEM.BUS_D24 MEM.BUS_D25 MEM.BUS_D26 MEM.BUS_D27 MEM.BUS_D28 MEM.BUS_D29 MEM.BUS_D30 MEM.BUS_D31 MEM.BUS_NBE0 MEM.BUS_NBE1 MEM.BUS_NBE2 MEM.BUS_NBE3 MEM.BUS_NOE MEM.BUS_NWE MEM.BUS_SRAM_NCS
net class SRAM.NBE[3..0]: SRAM.NBE0 SRAM.NBE1 SRAM.NBE2 SRAM.NBE3
net class SRAM.D[31..0]: SRAM.D0 SRAM.D1 SRAM.D2 SRAM.D3 SRAM.D4 SRAM.D5 SRAM.D6 SRAM.D7 SRAM.D8 SRAM.D9 SRAM.D10 SRAM.D11 SRAM.D12 SRAM.D13 SRAM.D14 SRAM.D15 SRAM.D16 SRAM.D17 SRAM.D18 SRAM.D19 SRAM.D20 SRAM.D21 SRAM.D22 SRAM.D23 SRAM.D24 SRAM.D25 SRAM.D26 SRAM.D27 SRAM.D28 SRAM.D29 SRAM.D30 SRAM.D31
net class SRAM.A[18..0]: SRAM.A0 SRAM.A1 SRAM.A2 SRAM.A3 SRAM.A4 SRAM.A5 SRAM.A6 SRAM.A7 SRAM.A8 SRAM.A9 SRAM.A10 SRAM.A11 SRAM.A12 SRAM.A13 SRAM.A14 SRAM.A15 SRAM.A16 SRAM.A17 SRAM.A18
net class CM_SDRAM: MEM.BUS_A2 MEM.BUS_A3 MEM.BUS_A4 MEM.BUS_A5 MEM.BUS_A6 MEM.BUS_A7 MEM.BUS_A8 MEM.BUS_A9 MEM.BUS_A10 MEM.BUS_A11 MEM.BUS_A12 MEM.BUS_A13 MEM.BUS_A14 MEM.BUS_A15 MEM.BUS_A16 MEM.BUS_D0 MEM.BUS_D1 MEM.BUS_D2 MEM.BUS_D3 MEM.BUS_D4 MEM.BUS_D5 MEM.BUS_D6 MEM.BUS_D7 MEM.BUS_D8 MEM.BUS_D9 MEM.BUS_D10 MEM.BUS_D11 MEM.BUS_D12 MEM.BUS_D13 MEM.BUS_D14 MEM.BUS_D15 MEM.BUS_D16 MEM.BUS_D17 MEM.BUS_D18 MEM.BUS_D19 MEM.BUS_D20 MEM.BUS_D21 MEM.BUS_D22 MEM.BUS_D23 MEM.BUS_D24 MEM.BUS_D25 MEM.BUS_D26 MEM.BUS_D27 MEM.BUS_D28 MEM.BUS_D29 MEM.BUS_D30 MEM.BUS_D31 MEM.BUS_NBE0 MEM.BUS_NBE1 MEM.BUS_NBE2 MEM.BUS_NBE3 MEM.BUS_NWE MEM.BUS_SDRAM_CKE MEM.BUS_SDRAM_CLK MEM.BUS_SDRAM_NCAS MEM.BUS_SDRAM_NCS MEM.BUS_SDRAM_NRAS
net class CM_FLASH: MEM.BUS_A1 MEM.BUS_A2 MEM.BUS_A3 MEM.BUS_A4 MEM.BUS_A5 MEM.BUS_A6 MEM.BUS_A7 MEM.BUS_A8 MEM.BUS_A9 MEM.BUS_A10 MEM.BUS_A11 MEM.BUS_A12 MEM.BUS_A13 MEM.BUS_A14 MEM.BUS_A15 MEM.BUS_A16 MEM.BUS_A17 MEM.BUS_A18 MEM.BUS_A19 MEM.BUS_A20 MEM.BUS_A21 MEM.BUS_A22 MEM.BUS_A23 MEM.BUS_A24 MEM.BUS_D0 MEM.BUS_D1 MEM.BUS_D2 MEM.BUS_D3 MEM.BUS_D4 MEM.BUS_D5 MEM.BUS_D6 MEM.BUS_D7 MEM.BUS_D8 MEM.BUS_D9 MEM.BUS_D10 MEM.BUS_D11 MEM.BUS_D12 MEM.BUS_D13 MEM.BUS_D14 MEM.BUS_D15 MEM.BUS_FLASH_NBUSY MEM.BUS_FLASH_NCS MEM.BUS_FLASH_NRESET MEM.BUS_NOE MEM.BUS_NWE
component class IND_SRAM: C9_M C10_M C12_M C203 C204 C205 C206 C207 C208 C209 C210 U22 U23
component class COM_SRAM: C227 C228 C229 C230 C231 C232 C233 C234 U27 U28
component class COM_SDRAM: C219 C220 C221 C222 C223 C224 C225 C226 U2_CMx U3_CMx U25 U26
component class SERIAL_FLASH: C199 C200 C201 C202 U20 U21
component class COM_FLASH: C211 C212 C213 C214 C215 C216 U24
net class SPI: PBSPI.DIN PBSPI.DOUT PBSPI.SCLK
net class PBSPI: PBSPI.DIN PBSPI.DOUT PBSPI.SCLK
net class PBCTRLC.SPI_CS_N[1..0]: PBCTRLC.SPI_CS_N0 PBCTRLC.SPI_CS_N1
net class PBCTRLB.SPI_CS_N[1..0]: PBCTRLB.SPI_CS_N0 PBCTRLB.SPI_CS_N1
net class PBCTRLA.SPI_CS_N[1..0]: PBCTRLA.SPI_CS_N0 PBCTRLA.SPI_CS_N1
component class "JTAG CONFIG3": R226 R227 R228 R229 R230 R231 R232 R233 R234 R235 R236 R237 R238 R239 R240 R241 R242 R243
component class "JTAG CONFIG2": R208 R209 R210 R211 R212 R213 R214 R215 R216 R217 R218 R219 R220 R221 R222 R223 R224 R225
component class "JTAG CONFIG1": R190 R191 R192 R193 R194 R195 R196 R197 R198 R199 R200 R201 R202 R203 R204 R205 R206 R207
net class AOUTB: AOUTB.L AOUTB.R
net class AOUTA: AOUTA.L AOUTA.R
net class AOUT_HOST: AOUT_HOST.L AOUT_HOST.R
component class LCDTFT: C114 C115 C116 C117 C118 PL1_TF Q1 Q2 Q3 Q4 R40 R41 R42 R43 R44 R45 R46 R47 R48 R49 R50 R51 U6 VR1
component class RS232: C153 C154 C155 C156 R71 R72 U13
component class MOUSE: C170 R88 R89 R90 R91
component class KEYBOARD: C169 R84 R85 R86 R87
component class PPORT: C1_PP C2_PP C3_PP C4_PP C5_PP C6_PP C7_PP C8_PP C9_PP C10_PP C11_PP C12_PP R21 R22 R23 R24 R25 R26 R27 R28 R29 R30 R31 R32 R33 R34 R35 R36 R37 R38 R39
component class MOUNTS: "Altium Logo BOT1" "Altium Logo Top1" FD1 FD2 FD3 LAYERGAUGE LAYERGAUGE1 LAYERGAUGE2 LB1 LIVE_DESIGN_DECAL1 LOGO1 LOGO2 MH1 MH2 MH3 MH4 MH5 MH6 MH7 MH8 PB_MH1 PB_MH2 PB_MH3 PB_MH4 PB_MH5 PB_MH6 PB_MH7 PB_MH8 PB_MH9 PB_MH10 PB_MH11 PB_MH12 PB_MH13 PB_MH14 "SRKH LOGO"
component class PSU: C1 C2 C3 C4 C217 C218 D1 GP1 GP2 GP3 GP4 NT1
component class HOSTJTAG: R280 R281 R282 R283 R284 R285 R286 R287 R288 R289 R290 R291 R292 R293 R294 R295
component class DIPSWITCH: R145 R146 R147 R148 R149 R150 R151 R152 SW7
component class ADCDAC: C16 JP1 NT2 R6 R7 R8 R9 R10
component class CON_LCDTFT: LCD1
component class CON_MOUSE: J6
component class CON_KEYBOARD: J5
component class CON_ADCDAC: TS1
component class CON_IO: JP4 JP5 UH1 UH2
component class CON_ADCDAC_EXTEND: HDR7
component class CLK_PLL: C12 C13 C14 C15 R3 R4 R5 U3 Y2
component class CAN: C4_AD C5_AD C6_AD C7_AD C123 C124 C125 C126 C127 CTS1 JP2 R53 R54 R55 RTS1 RXD1 TXD1 U8
component class AUDIO_AMP: C171 C172 C173 C175 C176 C178 C179 C181 C182 C184 C185 C186 C188 C189 C191 C192 LS_L LS_R NT4 R108 R109 R112 R113 R114 R115 R117 R118 R119 R121 R124 R125 R126 R128 R129 R133 R134 TP13 TP14 VR2
net class USER_LED: USER_LED.L0 USER_LED.L1 USER_LED.L2 USER_LED.L3 USER_LED.L4 USER_LED.L5 USER_LED.L6 USER_LED.L7
net class HOST_LED: HOST_LED.L0 HOST_LED.L1 HOST_LED.L2 HOST_LED.L3 HOST_LED.L4 HOST_LED.L5 HOST_LED.L6 HOST_LED.L7
net class USER_LED.L[7..0]: USER_LED.L0 USER_LED.L1 USER_LED.L2 USER_LED.L3 USER_LED.L4 USER_LED.L5 USER_LED.L6 USER_LED.L7
net class HOST_LED.L[7..0]: HOST_LED.L0 HOST_LED.L1 HOST_LED.L2 HOST_LED.L3 HOST_LED.L4 HOST_LED.L5 HOST_LED.L6 HOST_LED.L7
component class HOST_LEDS: LED1 LED2 LED3 LED4 LED5 LED6 LED7 LED8 R92 R93 R94 R95 R96 R97 R98 R99
net class TFT#: TFT#.BLUE0 TFT#.BLUE1 TFT#.BLUE2 TFT#.BLUE3 TFT#.BLUE4 TFT#.CL1 TFT#.CL2 TFT#.CL3 TFT#.DISP_ON TFT#.GREEN0 TFT#.GREEN1 TFT#.GREEN2 TFT#.GREEN3 TFT#.GREEN4 TFT#.GREEN5 TFT#.LED_C_L TFT#.LED_C_R TFT#.M TFT#.POL TFT#.RED0 TFT#.RED1 TFT#.RED2 TFT#.RED3 TFT#.RED4 TFT#.STH TFT#.STV TFT#.V0 TFT#.V4 TFT#.V5 TFT#.V9 TFT#.VCOM TFT#.X_MINUS TFT#.X_PLUS TFT#.Y_MINUS TFT#.Y_PLUS
net class TFT#.RED[4..0]: TFT#.RED0 TFT#.RED1 TFT#.RED2 TFT#.RED3 TFT#.RED4
net class TFT#.GREEN[5..0]: TFT#.GREEN0 TFT#.GREEN1 TFT#.GREEN2 TFT#.GREEN3 TFT#.GREEN4 TFT#.GREEN5
net class TFT#.BLUE[4..0]: TFT#.BLUE0 TFT#.BLUE1 TFT#.BLUE2 TFT#.BLUE3 TFT#.BLUE4
component class DAC: C17 U4
component class ADC: C5 C6 C7 C8 C9 U1
component class FPGA_PRGSETUP_1: R11 R12 R13 R14 R15 R16
component class FPGA_CONFIGFLASH_1: C119 C120 C121 C122 R52 TFT#.RED3 U7
component class DECOUPLING_CAPS_3V3_1: C54 C55 C56 C57 C58 C59 C60 C61 C62 C63 C64 C65 C66 C67 C68 C69 C70 C71 C72 C73 C74 C75 C76 C77 C78 C79 C80 C81 C82 C83 C84 C85 C86 C87 C88 C89 C90 C91 C92 C93 C94 C95 C96 C97 C98 C99 C100 C101 C102 C103 C104 C105 C106 C107 C108 C109 C110 C111 C112 C113
component class DECOUPLING_CAPS_2V5_1: C34 C35 C36 C37 C38 C39 C40 C41 C42 C43 C44 C45 C46 C47 C48 C49 C50 C51 C52 C53
component class DECOUPLING_CAPS_1V2_1: C18 C19 C20 C21 C22 C23 C24 C25 C26 C27 C28 C29 C30 C31 C32 C33
net class PWRNET: 1V2 1V8 2V5 3V3 5V0 5VUSW AGND GND VCCX
pad class "GND Net Link Pads": NT1-1 NT1-2 NT2-1 NT2-2
pad class Connector_Slot_Pads: J6-1 J6-3 J7-1 J7-2 J7-3 U1MIC-6
polygon class HeatsinkPolygons: POWER-BL-1V2 POWER-BL-1V8 POWER-BL-2V5 POWER-BL-3V3 POWER-BL-VCCX POWER-TL-1V2 POWER-TL-1V8 POWER-TL-2V5 POWER-TL-3V3 POWER-TL-VCCX
net class DAU_TFT.BLUE[4..0]: DAU_TFT.BLUE0 DAU_TFT.BLUE1 DAU_TFT.BLUE2 DAU_TFT.BLUE3 DAU_TFT.BLUE4
net class DAU_TFT.GREEN[5..0]: DAU_TFT.GREEN0 DAU_TFT.GREEN1 DAU_TFT.GREEN2 DAU_TFT.GREEN3 DAU_TFT.GREEN4 DAU_TFT.GREEN5
net class DAU_TFT.RED[4..0]: DAU_TFT.RED0 DAU_TFT.RED1 DAU_TFT.RED2 DAU_TFT.RED3 DAU_TFT.RED4
net class DAU_SPI: DAU_SPI.CLK DAU_SPI.DIN DAU_SPI.DOUT DAU_SPI.MODE DAU_SPI.SEL
net class DAU_TFT: DAU_TFT.BLIGHT DAU_TFT.BLUE0 DAU_TFT.BLUE1 DAU_TFT.BLUE2 DAU_TFT.BLUE3 DAU_TFT.BLUE4 DAU_TFT.CL1 DAU_TFT.CL2 DAU_TFT.CL3 DAU_TFT.DISP_ON DAU_TFT.GREEN0 DAU_TFT.GREEN1 DAU_TFT.GREEN2 DAU_TFT.GREEN3 DAU_TFT.GREEN4 DAU_TFT.GREEN5 DAU_TFT.IRQ DAU_TFT.M DAU_TFT.MUX DAU_TFT.POL DAU_TFT.RED0 DAU_TFT.RED1 DAU_TFT.RED2 DAU_TFT.RED3 DAU_TFT.RED4 DAU_TFT.STH DAU_TFT.STV
net class TFT: TFT#.BLUE0 TFT#.BLUE1 TFT#.BLUE2 TFT#.BLUE3 TFT#.BLUE4 TFT#.CL1 TFT#.CL2 TFT#.CL3 TFT#.DISP_ON TFT#.GREEN0 TFT#.GREEN1 TFT#.GREEN2 TFT#.GREEN3 TFT#.GREEN4 TFT#.GREEN5 TFT#.M TFT#.POL TFT#.RED0 TFT#.RED1 TFT#.RED2 TFT#.RED3 TFT#.RED4 TFT#.STH TFT#.STV TFT.BLIGHT TFT.IRQ
component class COMP_1V2: C145
component class PBA: EXTHDR1 R142
component class PBB: EXTHDR2 R143
component class PBC: EXTHDR3 R144
net class JTAG: JTAG.DETECTPBA JTAG.DETECTPBB JTAG.DETECTPBC JTAG.HARD.TCKPBA JTAG.HARD.TCKPBB JTAG.HARD.TCKPBC JTAG.HARD.TDIPBA JTAG.HARD.TDIPBB JTAG.HARD.TDIPBC JTAG.HARD.TDOPBA JTAG.HARD.TDOPBB JTAG.HARD.TDOPBC JTAG.HARD.TMSPBA JTAG.HARD.TMSPBB JTAG.HARD.TMSPBC JTAG.SOFT.TCKPBA JTAG.SOFT.TCKPBB JTAG.SOFT.TCKPBC JTAG.SOFT.TDIPBA JTAG.SOFT.TDIPBB JTAG.SOFT.TDIPBC JTAG.SOFT.TDOPBA JTAG.SOFT.TDOPBB JTAG.SOFT.TDOPBC JTAG.SOFT.TMSPBA JTAG.SOFT.TMSPBB JTAG.SOFT.TMSPBC "RS232_CON.DCD P1" "RS232_CON.DSR P6" "RS232_CON.DTR P4" "RS232_CON.SGND P5"
net class USB#: USB#.DMINUS USB#.DPLUS USB#.VBUS
net class USB.D[15..0]: USB.D0 USB.D1 USB.D2 USB.D3 USB.D4 USB.D5 USB.D6 USB.D7 USB.D8 USB.D9 USB.D10 USB.D11 USB.D12 USB.D13 USB.D14 USB.D15
net class USB: USB.D0 USB.D1 USB.D2 USB.D3 USB.D4 USB.D5 USB.D6 USB.D7 USB.D8 USB.D9 USB.D10 USB.D11 USB.D12 USB.D13 USB.D14 USB.D15 USB.FIFOADR0 USB.FIFOADR1 USB.FIFOADR2 USB.FLAGA USB.FLAGB USB.FLAGC USB.FLAGD_CS_N USB.IFCLK USB.INT_N USB.PKTEND USB.RD_N USB.READY USB.RESET_N USB.SLOE USB.VBUS USB.WR_N USB.XTALIN USB.XTALOUT
component class CON_SD: J8 R82 R83
net class CAN#: "CAN#.CAN_GND P3" CAN#.CAN_H CAN#.CAN_L "CAN#.GND P6"
net class CAN: CAN.RXD CAN.TXD
net class HJTAG#: HJTAG#.HARD.TCK HJTAG#.HARD.TDI HJTAG#.HARD.TDO HJTAG#.HARD.TMS HJTAG#.SOFT.TCK HJTAG#.SOFT.TDI HJTAG#.SOFT.TDO HJTAG#.SOFT.TMS
net class HJTAG: HJTAG.HARD.TCK HJTAG.HARD.TDI HJTAG.HARD.TDO HJTAG.HARD.TMS HJTAG.SOFT.TCK HJTAG.SOFT.TDI HJTAG.SOFT.TDO HJTAG.SOFT.TMS
net class KEYBOARD#: KEYBOARD#.CLOCK KEYBOARD#.DATA
net class KEYBOARD: KEYBOARD.CLOCK KEYBOARD.DATA
net class MOUSE#: MOUSE#.CLOCK MOUSE#.DATA
net class MOUSE: MOUSE.CLOCK MOUSE.DATA
net class RS232#: RS232#.CTS RS232#.DCD "RS232#.DCD P1" "RS232#.DSR P6" "RS232#.DTR P4" RS232#.RI RS232#.RTS RS232#.RXD "RS232#.SGND P5" RS232#.TXD
net class RS232: RS232.CTS "RS232.DCD P1" "RS232.DSR P6" "RS232.DTR P4" "RS232.RI P9" RS232.RTS RS232.RXD "RS232.SGND P5" RS232.TXD
net class SD.DAT[3..0]: SD.DAT0 SD.DAT1 SD.DAT2 SD.DAT3
net class SD: SD.CLK SD.CMD SD.DAT0 SD.DAT1 SD.DAT2 SD.DAT3 SD.DETECT SD.PROTECT
net class TALK#: TALK#.MASTER.CNCT TALK#.MASTER.MODE TALK#.MASTER.TCK TALK#.MASTER.TDI TALK#.MASTER.TDO TALK#.MASTER.TMS TALK#.SLAVE.CNCT TALK#.SLAVE.MODE TALK#.SLAVE.TCK TALK#.SLAVE.TDI TALK#.SLAVE.TDO TALK#.SLAVE.TMS
net class TALK: TALK#.MASTER.MODE TALK#.MASTER.TCK TALK#.MASTER.TDI TALK#.MASTER.TMS TALK#.SLAVE.TDO TALK.MASTER.CNCT TALK.MASTER.TDO TALK.SLAVE.CNCT TALK.SLAVE.MODE TALK.SLAVE.TCK TALK.SLAVE.TDI TALK.SLAVE.TMS
net class UBA#: UBA#.DETECT UBA#.HARD.TCK UBA#.HARD.TDI UBA#.HARD.TDO UBA#.HARD.TMS UBA#.SOFT.TCK UBA#.SOFT.TDI UBA#.SOFT.TDO UBA#.SOFT.TMS
net class UBA: UBA.DETECT UBA.HARD.TCK UBA.HARD.TDI UBA.HARD.TDO UBA.HARD.TMS UBA.SOFT.TCK UBA.SOFT.TDI UBA.SOFT.TDO UBA.SOFT.TMS
net class UBB#: UBB#.DETECT UBB#.HARD.TCK UBB#.HARD.TDI UBB#.HARD.TDO UBB#.HARD.TMS UBB#.SOFT.TCK UBB#.SOFT.TDI UBB#.SOFT.TDO UBB#.SOFT.TMS
net class UBB: UBB.DETECT UBB.HARD.TCK UBB.HARD.TDI UBB.HARD.TDO UBB.HARD.TMS UBB.SOFT.TCK UBB.SOFT.TDI UBB.SOFT.TDO UBB.SOFT.TMS
channel class PC_PS2: KEYBOARD MOUSE
component class CON_RS232: J9
channel class CON_USERJTAG_10WBOXHDRRAM: CON_UBA CON_USERBOARDB
component class CON_BATT: BT1
component class CON_USB: J4
net class DEBA.D[7..0]: DEBA.D0 DEBA.D1 DEBA.D2 DEBA.D3 DEBA.D4 DEBA.D5 DEBA.D6 DEBA.D7
net class DEBB.D[7..0]: DEBB.D0 DEBB.D1 DEBB.D2 DEBB.D3 DEBB.D4 DEBB.D5 DEBB.D6 DEBB.D7
net class DEBA: DEBA.D0 DEBA.D1 DEBA.D2 DEBA.D3 DEBA.D4 DEBA.D5 DEBA.D6 DEBA.D7
net class DEBB: DEBB.D0 DEBB.D1 DEBB.D2 DEBB.D3 DEBB.D4 DEBB.D5 DEBB.D6 DEBB.D7
channel class CON_DEBUG_10WBOXHDRRAM: CON_DEBUGA CON_DEBUGB
component class CON_PC_PPORT: HDR6
component class CON_NANOTALK: HDR4 HDR5
net class PPRT.D[7..0]: PPRT.D0 PPRT.D1 PPRT.D2 PPRT.D3 PPRT.D4 PPRT.D5 PPRT.D6 PPRT.D7
net class PPRT#.D[7..0]: PPRT#.D0 PPRT#.D1 PPRT#.D2 PPRT#.D3 PPRT#.D4 PPRT#.D5 PPRT#.D6 PPRT#.D7
net class PPRT#: PPRT#.ACK PPRT#.AUTOFD PPRT#.BUSY PPRT#.D0 PPRT#.D1 PPRT#.D2 PPRT#.D3 PPRT#.D4 PPRT#.D5 PPRT#.D6 PPRT#.D7 PPRT#.DETECT PPRT#.ERROR PPRT#.INIT PPRT#.ONE_WIRE_P PPRT#.PE PPRT#.SELECT PPRT#.SELECTIN PPRT#.STROBE
net class PPRT: PPRT.ACK PPRT.AUTOFD PPRT.BUSY PPRT.D0 PPRT.D1 PPRT.D2 PPRT.D3 PPRT.D4 PPRT.D5 PPRT.D6 PPRT.D7 PPRT.ERROR PPRT.INIT PPRT.PE PPRT.PLUG PPRT.SELECT PPRT.SELECTIN PPRT.STROBE
component class PDA_SWITCHES: IC1 R153 R154 R155 R156 R157 SW1 SW2 SW3 SW4 SW5
net class DIPSW.D[7..0]: DIPSW.D0 DIPSW.D1 DIPSW.D2 DIPSW.D3 DIPSW.D4 DIPSW.D5 DIPSW.D6 DIPSW.D7
net class DAU_PROG.ID[3..0]: DAU_PROG.ID0 DAU_PROG.ID1 DAU_PROG.ID2 DAU_PROG.ID3
net class DAU_PROG.M[2..0]: DAU_PROG.M0 DAU_PROG.M1 DAU_PROG.M2
component class DB_RESET: R158 SW8
component class HOST_RESET: R159 SW9
net class DAU_JTAG: DAU_JTAG.HARD.TCK DAU_JTAG.HARD.TDI DAU_JTAG.HARD.TDO DAU_JTAG.HARD.TMS DAU_JTAG.SOFT.TCK DAU_JTAG.SOFT.TDI DAU_JTAG.SOFT.TDO DAU_JTAG.SOFT.TMS
net class DAU_PROG: DAU_PROG.CCLK DAU_PROG.DIN DAU_PROG.DONE DAU_PROG.ID0 DAU_PROG.ID1 DAU_PROG.ID2 DAU_PROG.ID3 DAU_PROG.INIT DAU_PROG.INSTALLED DAU_PROG.M0 DAU_PROG.M1 DAU_PROG.M2 DAU_PROG.PROG_CLK DAU_PROG.PROG_PWR_ON DAU_PROG.PROGRAM
net class DIPSW: DIPSW.D0 DIPSW.D1 DIPSW.D2 DIPSW.D3 DIPSW.D4 DIPSW.D5 DIPSW.D6 DIPSW.D7
channel class NB2_PBCON: PBA PBB PBC
net class AOUT_PBA: AOUTA.L AOUTA.R
net class AOUT_PBB: AOUTB.L AOUTB.R
net class UIO.IO[35..0]: UIO.IO0 UIO.IO1 UIO.IO2 UIO.IO3 UIO.IO4 UIO.IO5 UIO.IO6 UIO.IO7 UIO.IO8 UIO.IO9 UIO.IO10 UIO.IO11 UIO.IO12 UIO.IO13 UIO.IO14 UIO.IO15 UIO.IO16 UIO.IO17 UIO.IO18 UIO.IO19 UIO.IO20 UIO.IO21 UIO.IO22 UIO.IO23 UIO.IO24 UIO.IO25 UIO.IO26 UIO.IO27 UIO.IO28 UIO.IO29 UIO.IO30 UIO.IO31 UIO.IO32 UIO.IO33 UIO.IO34 UIO.IO35
net class UIO: UIO.IO0 UIO.IO1 UIO.IO2 UIO.IO3 UIO.IO4 UIO.IO5 UIO.IO6 UIO.IO7 UIO.IO8 UIO.IO9 UIO.IO10 UIO.IO11 UIO.IO12 UIO.IO13 UIO.IO14 UIO.IO15 UIO.IO16 UIO.IO17 UIO.IO18 UIO.IO19 UIO.IO20 UIO.IO21 UIO.IO22 UIO.IO23 UIO.IO24 UIO.IO25 UIO.IO26 UIO.IO27 UIO.IO28 UIO.IO29 UIO.IO30 UIO.IO31 UIO.IO32 UIO.IO33 UIO.IO34 UIO.IO35
component class NB_ID: D12 R160 R161 U19
net class EXT_A.D[49..0]: EXT_A.D0 EXT_A.D1 EXT_A.D2 EXT_A.D3 EXT_A.D4 EXT_A.D5 EXT_A.D6 EXT_A.D7 EXT_A.D8 EXT_A.D9 EXT_A.D10 EXT_A.D11 EXT_A.D12 EXT_A.D13 EXT_A.D14 EXT_A.D15 EXT_A.D16 EXT_A.D17 EXT_A.D18 EXT_A.D19 EXT_A.D20 EXT_A.D21 EXT_A.D22 EXT_A.D23 EXT_A.D24 EXT_A.D25 EXT_A.D26 EXT_A.D27 EXT_A.D28 EXT_A.D29 EXT_A.D30 EXT_A.D31 EXT_A.D32 EXT_A.D33 EXT_A.D34 EXT_A.D35 EXT_A.D36 EXT_A.D37 EXT_A.D38 EXT_A.D39 EXT_A.D40 EXT_A.D41 EXT_A.D42 EXT_A.D43 EXT_A.D44 EXT_A.D45 EXT_A.D46 EXT_A.D47 EXT_A.D48 EXT_A.D49
net class EXT_A: EXT_A.D0 EXT_A.D1 EXT_A.D2 EXT_A.D3 EXT_A.D4 EXT_A.D5 EXT_A.D6 EXT_A.D7 EXT_A.D8 EXT_A.D9 EXT_A.D10 EXT_A.D11 EXT_A.D12 EXT_A.D13 EXT_A.D14 EXT_A.D15 EXT_A.D16 EXT_A.D17 EXT_A.D18 EXT_A.D19 EXT_A.D20 EXT_A.D21 EXT_A.D22 EXT_A.D23 EXT_A.D24 EXT_A.D25 EXT_A.D26 EXT_A.D27 EXT_A.D28 EXT_A.D29 EXT_A.D30 EXT_A.D31 EXT_A.D32 EXT_A.D33 EXT_A.D34 EXT_A.D35 EXT_A.D36 EXT_A.D37 EXT_A.D38 EXT_A.D39 EXT_A.D40 EXT_A.D41 EXT_A.D42 EXT_A.D43 EXT_A.D44 EXT_A.D45 EXT_A.D46 EXT_A.D47 EXT_A.D48 EXT_A.D49
net class EXT_B.D[49..0]: EXT_B.D0 EXT_B.D1 EXT_B.D2 EXT_B.D3 EXT_B.D4 EXT_B.D5 EXT_B.D6 EXT_B.D7 EXT_B.D8 EXT_B.D9 EXT_B.D10 EXT_B.D11 EXT_B.D12 EXT_B.D13 EXT_B.D14 EXT_B.D15 EXT_B.D16 EXT_B.D17 EXT_B.D18 EXT_B.D19 EXT_B.D20 EXT_B.D21 EXT_B.D22 EXT_B.D23 EXT_B.D24 EXT_B.D25 EXT_B.D26 EXT_B.D27 EXT_B.D28 EXT_B.D29 EXT_B.D30 EXT_B.D31 EXT_B.D32 EXT_B.D33 EXT_B.D34 EXT_B.D35 EXT_B.D36 EXT_B.D37 EXT_B.D38 EXT_B.D39 EXT_B.D40 EXT_B.D41 EXT_B.D42 EXT_B.D43 EXT_B.D44 EXT_B.D45 EXT_B.D46 EXT_B.D47 EXT_B.D48 EXT_B.D49
net class EXT_B: EXT_B.D0 EXT_B.D1 EXT_B.D2 EXT_B.D3 EXT_B.D4 EXT_B.D5 EXT_B.D6 EXT_B.D7 EXT_B.D8 EXT_B.D9 EXT_B.D10 EXT_B.D11 EXT_B.D12 EXT_B.D13 EXT_B.D14 EXT_B.D15 EXT_B.D16 EXT_B.D17 EXT_B.D18 EXT_B.D19 EXT_B.D20 EXT_B.D21 EXT_B.D22 EXT_B.D23 EXT_B.D24 EXT_B.D25 EXT_B.D26 EXT_B.D27 EXT_B.D28 EXT_B.D29 EXT_B.D30 EXT_B.D31 EXT_B.D32 EXT_B.D33 EXT_B.D34 EXT_B.D35 EXT_B.D36 EXT_B.D37 EXT_B.D38 EXT_B.D39 EXT_B.D40 EXT_B.D41 EXT_B.D42 EXT_B.D43 EXT_B.D44 EXT_B.D45 EXT_B.D46 EXT_B.D47 EXT_B.D48 EXT_B.D49
net class EXT_C.D[49..0]: EXT_C.D0 EXT_C.D1 EXT_C.D2 EXT_C.D3 EXT_C.D4 EXT_C.D5 EXT_C.D6 EXT_C.D7 EXT_C.D8 EXT_C.D9 EXT_C.D10 EXT_C.D11 EXT_C.D12 EXT_C.D13 EXT_C.D14 EXT_C.D15 EXT_C.D16 EXT_C.D17 EXT_C.D18 EXT_C.D19 EXT_C.D20 EXT_C.D21 EXT_C.D22 EXT_C.D23 EXT_C.D24 EXT_C.D25 EXT_C.D26 EXT_C.D27 EXT_C.D28 EXT_C.D29 EXT_C.D30 EXT_C.D31 EXT_C.D32 EXT_C.D33 EXT_C.D34 EXT_C.D35 EXT_C.D36 EXT_C.D37 EXT_C.D38 EXT_C.D39 EXT_C.D40 EXT_C.D41 EXT_C.D42 EXT_C.D43 EXT_C.D44 EXT_C.D45 EXT_C.D46 EXT_C.D47 EXT_C.D48 EXT_C.D49
net class EXT_C: EXT_C.D0 EXT_C.D1 EXT_C.D2 EXT_C.D3 EXT_C.D4 EXT_C.D5 EXT_C.D6 EXT_C.D7 EXT_C.D8 EXT_C.D9 EXT_C.D10 EXT_C.D11 EXT_C.D12 EXT_C.D13 EXT_C.D14 EXT_C.D15 EXT_C.D16 EXT_C.D17 EXT_C.D18 EXT_C.D19 EXT_C.D20 EXT_C.D21 EXT_C.D22 EXT_C.D23 EXT_C.D24 EXT_C.D25 EXT_C.D26 EXT_C.D27 EXT_C.D28 EXT_C.D29 EXT_C.D30 EXT_C.D31 EXT_C.D32 EXT_C.D33 EXT_C.D34 EXT_C.D35 EXT_C.D36 EXT_C.D37 EXT_C.D38 EXT_C.D39 EXT_C.D40 EXT_C.D41 EXT_C.D42 EXT_C.D43 EXT_C.D44 EXT_C.D45 EXT_C.D46 EXT_C.D47 EXT_C.D48 EXT_C.D49
net class MEM.BUS_NBE[3..0]: MEM.BUS_NBE0 MEM.BUS_NBE1 MEM.BUS_NBE2 MEM.BUS_NBE3
net class MEM: MEM.BUS_A1 MEM.BUS_A2 MEM.BUS_A3 MEM.BUS_A4 MEM.BUS_A5 MEM.BUS_A6 MEM.BUS_A7 MEM.BUS_A8 MEM.BUS_A9 MEM.BUS_A10 MEM.BUS_A11 MEM.BUS_A12 MEM.BUS_A13 MEM.BUS_A14 MEM.BUS_A15 MEM.BUS_A16 MEM.BUS_A17 MEM.BUS_A18 MEM.BUS_A19 MEM.BUS_A20 MEM.BUS_A21 MEM.BUS_A22 MEM.BUS_A23 MEM.BUS_A24 MEM.BUS_D0 MEM.BUS_D1 MEM.BUS_D2 MEM.BUS_D3 MEM.BUS_D4 MEM.BUS_D5 MEM.BUS_D6 MEM.BUS_D7 MEM.BUS_D8 MEM.BUS_D9 MEM.BUS_D10 MEM.BUS_D11 MEM.BUS_D12 MEM.BUS_D13 MEM.BUS_D14 MEM.BUS_D15 MEM.BUS_D16 MEM.BUS_D17 MEM.BUS_D18 MEM.BUS_D19 MEM.BUS_D20 MEM.BUS_D21 MEM.BUS_D22 MEM.BUS_D23 MEM.BUS_D24 MEM.BUS_D25 MEM.BUS_D26 MEM.BUS_D27 MEM.BUS_D28 MEM.BUS_D29 MEM.BUS_D30 MEM.BUS_D31 MEM.BUS_FLASH_NBUSY MEM.BUS_FLASH_NCS MEM.BUS_FLASH_NRESET MEM.BUS_NBE0 MEM.BUS_NBE1 MEM.BUS_NBE2 MEM.BUS_NBE3 MEM.BUS_NOE MEM.BUS_NWE MEM.BUS_SDRAM_CKE MEM.BUS_SDRAM_CLK MEM.BUS_SDRAM_NCAS MEM.BUS_SDRAM_NCS MEM.BUS_SDRAM_NRAS MEM.BUS_SRAM_NCS
component class PSU_16V5: C139 C140 C141 C142 C143 C144 D5 L1 R63 R64 R65 TP8 U11
component class PSU_9V0: C132 C133 C134 R57 R58 R59 TP6 U9
component class PSU-7V5: C128 C129 C130 C131 D2 D3 R56 TP5
component class PSU_1V2: C145 C146 C147 C148 C149 C150 C151 C152 L2 R66 R67 R68 R69 R70 TP9 U12
component class PSU_1V8: C157 C158 C159 C160 D6 R73 R74 R75 TP10 U14
component class PSU_2V5: C161 C162 C163 C164 D7 R76 R77 R78 TP11 U15
component class PSU_3V3: C165 C166 C167 C168 D8 R79 R80 R81 TP12 U16
component class PSU_VCCX: C135 C136 C137 C138 D4 R60 R61 R62 TP7 U10
net class AD.AIN[3..0]: AD.AIN0 AD.AIN1 AD.AIN2 AD.AIN3
net class AD.AOUT[3..0]: AD.AOUT0 AD.AOUT1 AD.AOUT2 AD.AOUT3
net class AD: AD.AIN0 AD.AIN1 AD.AIN2 AD.AIN3 AD.AOUT0 AD.AOUT1 AD.AOUT2 AD.AOUT3 AD.I2C.SCL AD.I2C.SDA
net class AOUT: AIN.L AIN.R AOUTA.L AOUTA.R AOUTB.L AOUTB.R
net class CLOCKS: PBCTRLA.CLK.CLK0 PBCTRLA.CLK.CLK1 PBCTRLA.CLK.CLK2 PBCTRLA.CLK.EN PBCTRLB.CLK.CLK0 PBCTRLB.CLK.CLK1 PBCTRLB.CLK.CLK2 PBCTRLB.CLK.EN PBCTRLC.CLK.CLK0 PBCTRLC.CLK.CLK1 PBCTRLC.CLK.CLK2 PBCTRLC.CLK.EN
net class DAU_CLK: CLKPLL.CLK_FIXED CLKPLL.CLK_PROG DAU_CLK.FPGA_CLK1
net class I2C: AD.I2C.SCL AD.I2C.SDA
net class ONE_WIRE: PBCTRLA.1W.ID PBCTRLA.1W.PIO1 PBCTRLA.1W.PIO2 PBCTRLB.1W.ID PBCTRLB.1W.PIO1 PBCTRLB.1W.PIO2 PBCTRLC.1W.ID PBCTRLC.1W.PIO1 PBCTRLC.1W.PIO2
net class PBCTRLA.1W.PIO[1..2]: PBCTRLA.1W.PIO1 PBCTRLA.1W.PIO2
net class PBCTRLA.CLK.CLK[2..0]: PBCTRLA.CLK.CLK0 PBCTRLA.CLK.CLK1 PBCTRLA.CLK.CLK2
net class PBCTRLA.SPARE[1..4]: PBCTRLA.SPARE1 PBCTRLA.SPARE2 PBCTRLA.SPARE3 PBCTRLA.SPARE4
net class PBCTRLA: PBCTRLA.1W.ID PBCTRLA.1W.PIO1 PBCTRLA.1W.PIO2 PBCTRLA.CLK.CLK0 PBCTRLA.CLK.CLK1 PBCTRLA.CLK.CLK2 PBCTRLA.CLK.EN PBCTRLA.JTAG.DETECT PBCTRLA.JTAG.HARD.TCK PBCTRLA.JTAG.HARD.TDI PBCTRLA.JTAG.HARD.TDO PBCTRLA.JTAG.HARD.TMS PBCTRLA.JTAG.SOFT.TCK PBCTRLA.JTAG.SOFT.TDI PBCTRLA.JTAG.SOFT.TDO PBCTRLA.JTAG.SOFT.TMS PBCTRLA.SPARE1 PBCTRLA.SPARE2 PBCTRLA.SPARE3 PBCTRLA.SPARE4 PBCTRLA.SPI_CS_N0 PBCTRLA.SPI_CS_N1
net class PBCTRLB.1W.PIO[1..2]: PBCTRLB.1W.PIO1 PBCTRLB.1W.PIO2
net class PBCTRLB.CLK.CLK[2..0]: PBCTRLB.CLK.CLK0 PBCTRLB.CLK.CLK1 PBCTRLB.CLK.CLK2
net class PBCTRLB.SPARE[1..4]: PBCTRLB.SPARE1 PBCTRLB.SPARE2 PBCTRLB.SPARE3 PBCTRLB.SPARE4
net class PBCTRLB: PBCTRLB.1W.ID PBCTRLB.1W.PIO1 PBCTRLB.1W.PIO2 PBCTRLB.CLK.CLK0 PBCTRLB.CLK.CLK1 PBCTRLB.CLK.CLK2 PBCTRLB.CLK.EN PBCTRLB.JTAG.DETECT PBCTRLB.JTAG.HARD.TCK PBCTRLB.JTAG.HARD.TDI PBCTRLB.JTAG.HARD.TDO PBCTRLB.JTAG.HARD.TMS PBCTRLB.JTAG.SOFT.TCK PBCTRLB.JTAG.SOFT.TDI PBCTRLB.JTAG.SOFT.TDO PBCTRLB.JTAG.SOFT.TMS PBCTRLB.SPARE1 PBCTRLB.SPARE2 PBCTRLB.SPARE3 PBCTRLB.SPARE4 PBCTRLB.SPI_CS_N0 PBCTRLB.SPI_CS_N1
net class PBCTRLC.1W.PIO[1..2]: PBCTRLC.1W.PIO1 PBCTRLC.1W.PIO2
net class PBCTRLC.CLK.CLK[2..0]: PBCTRLC.CLK.CLK0 PBCTRLC.CLK.CLK1 PBCTRLC.CLK.CLK2
net class PBCTRLC.SPARE[1..4]: PBCTRLC.SPARE1 PBCTRLC.SPARE2 PBCTRLC.SPARE3 PBCTRLC.SPARE4
net class PBCTRLC: PBCTRLC.1W.ID PBCTRLC.1W.PIO1 PBCTRLC.1W.PIO2 PBCTRLC.CLK.CLK0 PBCTRLC.CLK.CLK1 PBCTRLC.CLK.CLK2 PBCTRLC.CLK.EN PBCTRLC.JTAG.DETECT PBCTRLC.JTAG.HARD.TCK PBCTRLC.JTAG.HARD.TDI PBCTRLC.JTAG.HARD.TDO PBCTRLC.JTAG.HARD.TMS PBCTRLC.JTAG.SOFT.TCK PBCTRLC.JTAG.SOFT.TDI PBCTRLC.JTAG.SOFT.TDO PBCTRLC.JTAG.SOFT.TMS PBCTRLC.SPARE1 PBCTRLC.SPARE2 PBCTRLC.SPARE3 PBCTRLC.SPARE4 PBCTRLC.SPI_CS_N0 PBCTRLC.SPI_CS_N1
net class AOUT_PBC: AIN.L AIN.R
net class AIN: AIN.L AIN.R AOUTC.L AOUTC.MIC AOUTC.R
net class AOUTC: AOUTC.L AOUTC.MIC AOUTC.R
component class "RT CLOCK": C10 C11 R1 R2 TP2 TP15 U2 Y1
component class USER_BOARD_A: R244 R245 R246 R247 R248 R249 R250 R251 R252 R253 R254 R255 R256 R257 R258 R259 R260 R261
component class USER_BOARD_B: R262 R263 R264 R265 R266 R267 R268 R269 R270 R271 R272 R273 R274 R275 R276 R277 R278 R279
net class CLKPLL: CLKPLL.CLK_FIXED CLKPLL.CLK_PROG CLKPLL.CS_N CLKPLL.DIN CLKPLL.SCLK
net class RTC: RTC.CS_N RTC.DIN RTC.DOUT RTC.RST_N RTC.SCLK
component class COMP_5V0: J1 J2 J3 SW6
component class CON_PSU: F1 J1 J2 J3 SW6 TP1
component class USER_LEDS: LED9 LED10 LED11 LED12 LED13 LED14 LED15 LED16 R100 R101 R102 R103 R104 R105 R106 R107
component class CON_DEBUGA: D9 DH1 F3
component class CON_DEBUGB: D10 DH2 F4
component class CON_HOSTJTAG: D11 F5 HDR3
component class CON_CAN: F2 J7 JP3

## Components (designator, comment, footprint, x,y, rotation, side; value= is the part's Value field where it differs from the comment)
"Altium Logo BOT1" "Altium" Logo-Altium 6737.94,635 r180 bottom
"Altium Logo Top1" "Altium" Logo-Altium 6948.68,727.45 r0 top
BT1 "CELLBATT 20mm HEADER" CELL_HOLDER 9597.44,5444.88 r180 top locked
C1 "220uF 10V" CAPC7343-STAR 5873.5,5290.53 r180 bottom locked
C2 "220uF 10V" CAPC7343-STAR 537.93,1136.74 r270 bottom
C3 "220uF 10V" CAPC7343-STAR 1968.5,4177.17 r0 bottom
C4 "220uF 10V" CAPC7343-STAR 2429.13,5972.44 r0 bottom locked
C5 "100pF 50V" CAPC1005-STAR 8270.97,1277.52 r90 bottom (schematic designator C2)
C6 "100pF 50V" CAPC1005-STAR 8370.97,1277.52 r90 bottom (schematic designator C3)
C7 "100pF 50V" CAPC1005-STAR 8470.97,1277.52 r90 bottom (schematic designator C4)
C8 "100pF 50V" CAPC1005-STAR 8570.97,1277.52 r90 bottom (schematic designator C5)
C9 "0.1uF 16V" CAPC1005-STAR 7514.54,1507.81 r270 bottom (schematic designator C1)
C10 "10uF 20V" CAPC3528-STAR 8690.56,4992.74 r270 bottom (schematic designator C2)
C11 "0.1uF 16V" CAPC1005-STAR 9305.73,4823.54 r180 bottom (schematic designator C3)
C12 "15pF 50V" CAPC1005-STAR 6799.21,2185.04 r0 bottom locked (schematic designator C1)
C13 "15pF 50V" CAPC1005-STAR 6311.02,2185.04 r180 bottom locked (schematic designator C2)
C14 "0.1uF 16V" CAPC1005-STAR 6307.09,2039.37 r180 bottom locked (schematic designator C4)
C15 "10uF 20V" CAPC3528-STAR 6801.5,2020.58 r270 bottom locked (schematic designator C3)
C16 "10uF 20V" CAPC3528-STAR 8329.94,1623 r180 bottom locked (schematic designator C1)
C17 "0.1uF 16V" CAPC1005-STAR 8314.2,1485.2 r180 bottom locked (schematic designator C1)
C18 "10uF 20V" CAPC3528-STAR 10621.45,3751.95 r270 bottom (schematic designator C42_FP)
C19 "10uF 20V" CAPC3528-STAR 10621.47,3130.01 r270 bottom (schematic designator C43_FP)
C20 "10uF 20V" CAPC3528-STAR 10303.13,4078.15 r0 bottom locked (schematic designator C103_FP)
C21 "10uF 20V" CAPC3528-STAR 9681.19,4078.16 r0 bottom (schematic designator C45_FP)
C22 "10uF 20V" CAPC3528-STAR 10295.25,2811.7 r0 bottom (schematic designator C104_FP)
C23 "10uF 20V" CAPC3528-STAR 9355.01,3137.88 r270 bottom (schematic designator C1_FP)
C24 "10uF 20V" CAPC3528-STAR 9673.32,2811.7 r0 bottom (schematic designator C2_FP)
C25 "10uF 20V" CAPC3528-STAR 9355.01,3759.81 r270 bottom locked (schematic designator C3_FP)
C26 "0.1uF 16V" CAPC1005-STAR 10216.54,3279.53 r45 bottom (schematic designator C5_FP)
C27 "0.1uF 16V" CAPC1005-STAR 9822.84,3216.53 r315 bottom (schematic designator C8_FP)
C28 "0.1uF 16V" CAPC1005-STAR 10216.54,3610.24 r315 bottom (schematic designator C9_FP)
C29 "0.1uF 16V" CAPC1005-STAR 9759.84,3610.24 r225 bottom (schematic designator C11_FP)
C30 "10nF 16V" CAPC1005-STAR 10153.54,3216.53 r225 bottom (schematic designator C13_FP)
C31 "10nF 16V" CAPC1005-STAR 9822.84,3673.23 r45 bottom (schematic designator C15_FP)
C32 "10nF 16V" CAPC1005-STAR 9759.84,3279.53 r135 bottom (schematic designator C16_FP)
C33 "10nF 16V" CAPC1005-STAR 10153.54,3673.23 r135 bottom (schematic designator C18_FP)
C34 "10uF 20V" CAPC3528-STAR 10555.25,2872.35 r225 bottom (schematic designator C44_FP)
C35 "10uF 20V" CAPC3528-STAR 9415.57,2877.92 r315 bottom (schematic designator C102_FP)
C36 "10uF 20V" CAPC3528-STAR 10560.82,4011.86 r315 bottom (schematic designator C20_FP)
C37 "10uF 20V" CAPC3528-STAR 9421.13,4017.43 r225 bottom (schematic designator C21_FP)
C38 "0.1uF 16V" CAPC1005-STAR 10216.85,3965.16 r0 bottom locked (schematic designator C22_FP)
C39 "0.1uF 16V" CAPC1005-STAR 10507.28,3673.54 r90 bottom locked (schematic designator C23_FP)
C40 "0.1uF 16V" CAPC1005-STAR 9468.49,3216.53 r270 bottom locked (schematic designator C24_FP)
C41 "0.1uF 16V" CAPC1005-STAR 9759.68,3963.45 r180 bottom (schematic designator C25_FP)
C42 "0.1uF 16V" CAPC1005-STAR 10216.85,2925.79 r0 bottom locked (schematic designator C26_FP)
C43 "10nF 16V" CAPC1005-STAR 10429.73,2953.47 r90 bottom locked (schematic designator C27_FP)
C44 "10nF 16V" CAPC1005-STAR 9469.09,3673.94 r90 bottom locked (schematic designator C28_FP)
C45 "10nF 16V" CAPC1005-STAR 9546.65,3936.3 r270 bottom locked (schematic designator C29_FP)
C46 "10nF 16V" CAPC1005-STAR 10428.54,3936.3 r270 bottom locked (schematic designator C30_FP)
C47 "10nF 16V" CAPC1005-STAR 9496.77,3003.35 r0 bottom locked (schematic designator C31_FP)
C48 "10nF 16V" CAPC1005-STAR 10479.61,3004.53 r180 bottom locked (schematic designator C32_FP)
C49 "10nF 16V" CAPC1005-STAR 10479.61,3886.42 r180 bottom locked (schematic designator C33_FP)
C50 "10nF 16V" CAPC1005-STAR 9547.84,2953.47 r90 bottom locked (schematic designator C34_FP)
C51 "10nF 16V" CAPC1005-STAR 10507.28,3215.83 r270 bottom locked (schematic designator C35_FP)
C52 "10nF 16V" CAPC1005-STAR 9759.13,2925.79 r180 bottom locked (schematic designator C36_FP)
C53 "10nF 16V" CAPC1005-STAR 9496.77,3885.24 r0 bottom locked (schematic designator C37_FP)
C54 "10uF 20V" CAPC3528-STAR 9984.3,2811.7 r0 bottom (schematic designator C38_FP)
C55 "10uF 20V" CAPC3528-STAR 10621.47,3441 r270 bottom (schematic designator C39_FP)
C56 "10uF 20V" CAPC3528-STAR 9992.16,4078.15 r0 bottom locked (schematic designator C40_FP)
C57 "10uF 20V" CAPC3528-STAR 9355.01,3448.87 r270 bottom (schematic designator C41_FP)
C58 "0.1uF 16V" CAPC1005-STAR 10224.68,3429.45 r0 bottom (schematic designator C72_FP)
C59 "0.1uF 16V" CAPC1005-STAR 9752.68,3460.45 r180 bottom (schematic designator C75_FP)
C60 "0.1uF 16V" CAPC1005-STAR 9972.44,3681.1 r90 bottom (schematic designator C76_FP)
C61 "0.1uF 16V" CAPC1005-STAR 9752.68,3429.45 r180 bottom (schematic designator C77_FP)
C62 "0.1uF 16V" CAPC1005-STAR 9973.68,3360.64 r270 bottom (schematic designator C78_FP)
C63 "0.1uF 16V" CAPC1005-STAR 10072.49,3429.45 r0 bottom (schematic designator C86_FP)
C64 "0.1uF 16V" CAPC1005-STAR 9903.87,3460.45 r180 bottom (schematic designator C90_FP)
C65 "0.1uF 16V" CAPC1005-STAR 10224.68,3460.45 r0 bottom (schematic designator C92_FP)
C66 "0.1uF 16V" CAPC1005-STAR 10003.94,3681.1 r90 bottom (schematic designator C93_FP)
C67 "0.1uF 16V" CAPC1005-STAR 10003.94,3208.66 r270 bottom (schematic designator C83_FP)
C68 "0.1uF 16V" CAPC1005-STAR 9972.44,3208.66 r270 bottom (schematic designator C82_FP)
C69 "0.1uF 16V" CAPC1005-STAR 10453.68,3090.45 r270 bottom (schematic designator C46_FP)
C70 "0.1uF 16V" CAPC1005-STAR 10342.68,2979.45 r0 bottom (schematic designator C47_FP)
C71 "0.1uF 16V" CAPC1005-STAR 10080.68,2960.45 r270 bottom (schematic designator C48_FP)
C72 "0.1uF 16V" CAPC1005-STAR 9503.68,3353.45 r180 bottom (schematic designator C49_FP)
C73 "0.1uF 16V" CAPC1005-STAR 10454.68,3799.45 r90 bottom (schematic designator C50_FP)
C74 "0.1uF 16V" CAPC1005-STAR 10474.68,3353.45 r0 bottom (schematic designator C51_FP)
C75 "0.1uF 16V" CAPC1005-STAR 9476.76,3092.36 r270 bottom (schematic designator C52_FP)
C76 "0.1uF 16V" CAPC1005-STAR 9896.68,2960.45 r270 bottom (schematic designator C53_FP)
C77 "0.1uF 16V" CAPC1005-STAR 9503.94,3530.91 r180 bottom locked (schematic designator C54_FP)
C78 "0.1uF 16V" CAPC1005-STAR 9633.68,3909.45 r180 bottom (schematic designator C55_FP)
C79 "0.1uF 16V" CAPC1005-STAR 10342.84,3906.1 r0 bottom locked (schematic designator C56_FP)
C80 "0.1uF 16V" CAPC1005-STAR 9526.97,3799.53 r90 bottom locked (schematic designator C57_FP)
C81 "0.1uF 16V" CAPC1005-STAR 9633.54,2983.66 r180 bottom locked (schematic designator C58_FP)
C82 "0.1uF 16V" CAPC1005-STAR 10475.68,3536.45 r0 bottom (schematic designator C59_FP)
C83 "0.1uF 16V" CAPC1005-STAR 10077.68,3929.45 r90 bottom (schematic designator C60_FP)
C84 "0.1uF 16V" CAPC1005-STAR 9897.68,3929.45 r90 bottom (schematic designator C61_FP)
C85 "10nF 16V" CAPC1005-STAR 9828.74,3429.14 r0 bottom (schematic designator C62_FP)
C86 "10nF 16V" CAPC1005-STAR 9972.44,3604.33 r270 bottom (schematic designator C63_FP)
C87 "10nF 16V" CAPC1005-STAR 10342.68,3956.31 r0 bottom (schematic designator C64_FP)
C88 "10nF 16V" CAPC1005-STAR 10342.68,2933.45 r0 bottom (schematic designator C65_FP)
C89 "10nF 16V" CAPC1005-STAR 9633.7,3956.31 r180 bottom (schematic designator C66_FP)
C90 "10nF 16V" CAPC1005-STAR 10474.68,3588.45 r0 bottom (schematic designator C67_FP)
C91 "10nF 16V" CAPC1005-STAR 10148.62,3460.63 r180 bottom (schematic designator C68_FP)
C92 "10nF 16V" CAPC1005-STAR 9972.68,3528.26 r90 bottom (schematic designator C69_FP)
C93 "10nF 16V" CAPC1005-STAR 10003.68,3528.26 r90 bottom (schematic designator C70_FP)
C94 "10nF 16V" CAPC1005-STAR 10003.94,3604.33 r270 bottom (schematic designator C71_FP)
C95 "10nF 16V" CAPC1005-STAR 10148.62,3429.13 r180 bottom (schematic designator C73_FP)
C96 "10nF 16V" CAPC1005-STAR 10072.49,3460.45 r0 bottom (schematic designator C74_FP)
C97 "10nF 16V" CAPC1005-STAR 9842.68,2960.45 r270 bottom (schematic designator C79_FP)
C98 "10nF 16V" CAPC1005-STAR 9526.97,3089.84 r270 bottom locked (schematic designator C80_FP)
C99 "10nF 16V" CAPC1005-STAR 9633.7,2933.45 r180 bottom (schematic designator C81_FP)
C100 "10nF 16V" CAPC1005-STAR 9972.44,3285.43 r90 bottom (schematic designator C84_FP)
C101 "10nF 16V" CAPC1005-STAR 10498.68,3799.45 r90 bottom (schematic designator C85_FP)
C102 "10nF 16V" CAPC1005-STAR 10474.68,3299.45 r0 bottom (schematic designator C101_FP)
C103 "10nF 16V" CAPC1005-STAR 10132.68,2960.45 r270 bottom (schematic designator C87_FP)
C104 "10nF 16V" CAPC1005-STAR 10003.94,3285.43 r90 bottom (schematic designator C88_FP)
C105 "10nF 16V" CAPC1005-STAR 9828.74,3460.63 r0 bottom (schematic designator C89_FP)
C106 "10nF 16V" CAPC1005-STAR 9476.76,3797.41 r90 bottom (schematic designator C100_FP)
C107 "10nF 16V" CAPC1005-STAR 9903.87,3429.45 r180 bottom (schematic designator C91_FP)
C108 "10nF 16V" CAPC1005-STAR 10503.94,3090.55 r270 bottom locked (schematic designator C99_FP)
C109 "10nF 16V" CAPC1005-STAR 9503.94,3591.14 r180 bottom locked (schematic designator C98_FP)
C110 "10nF 16V" CAPC1005-STAR 10003.68,3360.64 r270 bottom (schematic designator C94_FP)
C111 "10nF 16V" CAPC1005-STAR 10134.68,3929.45 r90 bottom (schematic designator C95_FP)
C112 "10nF 16V" CAPC1005-STAR 9842.68,3929.45 r90 bottom (schematic designator C96_FP)
C113 "10nF 16V" CAPC1005-STAR 9503.68,3299.45 r180 bottom (schematic designator C97_FP)
C114 "10uF 20V" CAPC3528-STAR 8876.3,1623 r180 bottom (schematic designator C2)
C115 "0.1uF 16V" CAPC1005-STAR 8181.1,2685.04 r270 bottom locked (schematic designator C17)
C116 "10uF 20V" CAPC3528-STAR 5952.76,2948.82 r90 bottom locked (schematic designator C3)
C117 "0.1uF 16V" CAPC1005-STAR 8984.25,3192.91 r180 bottom locked (schematic designator C18)
C118 "100pF 50V" CAPC1005-STAR 8177.17,2460.63 r180 bottom locked (schematic designator C1)
C119 "0.1uF 16V" CAPC1005-STAR 11062.99,4444.88 r90 bottom locked (schematic designator C1)
C120 "0.1uF 16V" CAPC1005-STAR 11208.66,4307.09 r90 bottom locked (schematic designator C2)
C121 "0.1uF 16V" CAPC1005-STAR 11082.68,4279.53 r90 bottom locked (schematic designator C3)
C122 "0.1uF 16V" CAPC1005-STAR 11208.66,4440.95 r90 bottom locked (schematic designator C4)
C123 "10uF 20V" CAPC3528-STAR 6610.3,4992.74 r270 bottom locked (schematic designator C3)
C124 "10uF 20V" CAPC3528-STAR 7107.83,4992.74 r270 bottom locked (schematic designator C2)
C125 "0.1uF 16V" CAPC1005-STAR 6800.01,4702 r180 bottom locked (schematic designator C4)
C126 "0.1uF 16V" CAPC1005-STAR 7156.74,5251.06 r0 bottom (schematic designator C1)
C127 "0.1uF 16V" CAPC1005-STAR 6907.16,5252.06 r0 bottom (schematic designator C9)
C128 "1uF 25V" CAPC3216-STAR 7027.56,2897.64 r270 bottom locked (schematic designator C2)
C129 "0.1uF 16V" CAPC1005-STAR 8389.76,2102.36 r270 bottom locked (schematic designator C3)
C130 "1uF 25V" CAPC3216-STAR 6972.44,2724.41 r0 bottom locked (schematic designator C1)
C131 "1uF 25V" CAPC3216-STAR 7283.46,2779.53 r90 bottom locked (schematic designator C4)
C132 "10uF 20V" CAPC3528-STAR 6346.46,2948.82 r90 bottom locked (schematic designator C1)
C133 "10uF 20V" CAPC3528-STAR 7551.06,2708.66 r0 bottom (schematic designator C3)
C134 "0.1uF 16V" CAPC1005-STAR 7492.13,2543.31 r0 bottom locked (schematic designator C2)
C135 "10uF 20V" CAPC3528-STAR 3019.69,1582.68 r0 bottom locked (schematic designator C1)
C136 "10uF 20V" CAPC3528-STAR 3019.68,1421.26 r0 bottom locked (schematic designator C2)
C137 "220uF 10V" CAPC7343-STAR 3098.68,2103.45 r0 bottom (schematic designator C3)
C138 "10uF 10V" CAPC2012-STAR 3283.56,1887.81 r270 bottom (schematic designator C4)
C139 "1uF 25V" CAPC3216-STAR 6503.94,2944.88 r270 bottom locked (schematic designator C1)
C140 "10uF 20V" CAPC3528-STAR 8240.16,4149.61 r90 bottom (schematic designator C2)
C141 "0.1uF 16V" CAPC1005-STAR 6035.43,2783.47 r0 bottom locked (schematic designator C3)
C142 "10uF 10V" CAPC2012-STAR 8106.75,4125.98 r270 bottom (schematic designator C4)
C143 "10uF 20V" CAPC3528-STAR 6149.61,2948.82 r90 bottom locked (schematic designator C5)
